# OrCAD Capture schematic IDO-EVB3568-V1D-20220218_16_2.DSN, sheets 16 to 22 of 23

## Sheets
16 P19. Ethernet-GEPHY_RGMII1_M1: size A2; note: Ethernet-GEPHY_RGMII1_M1
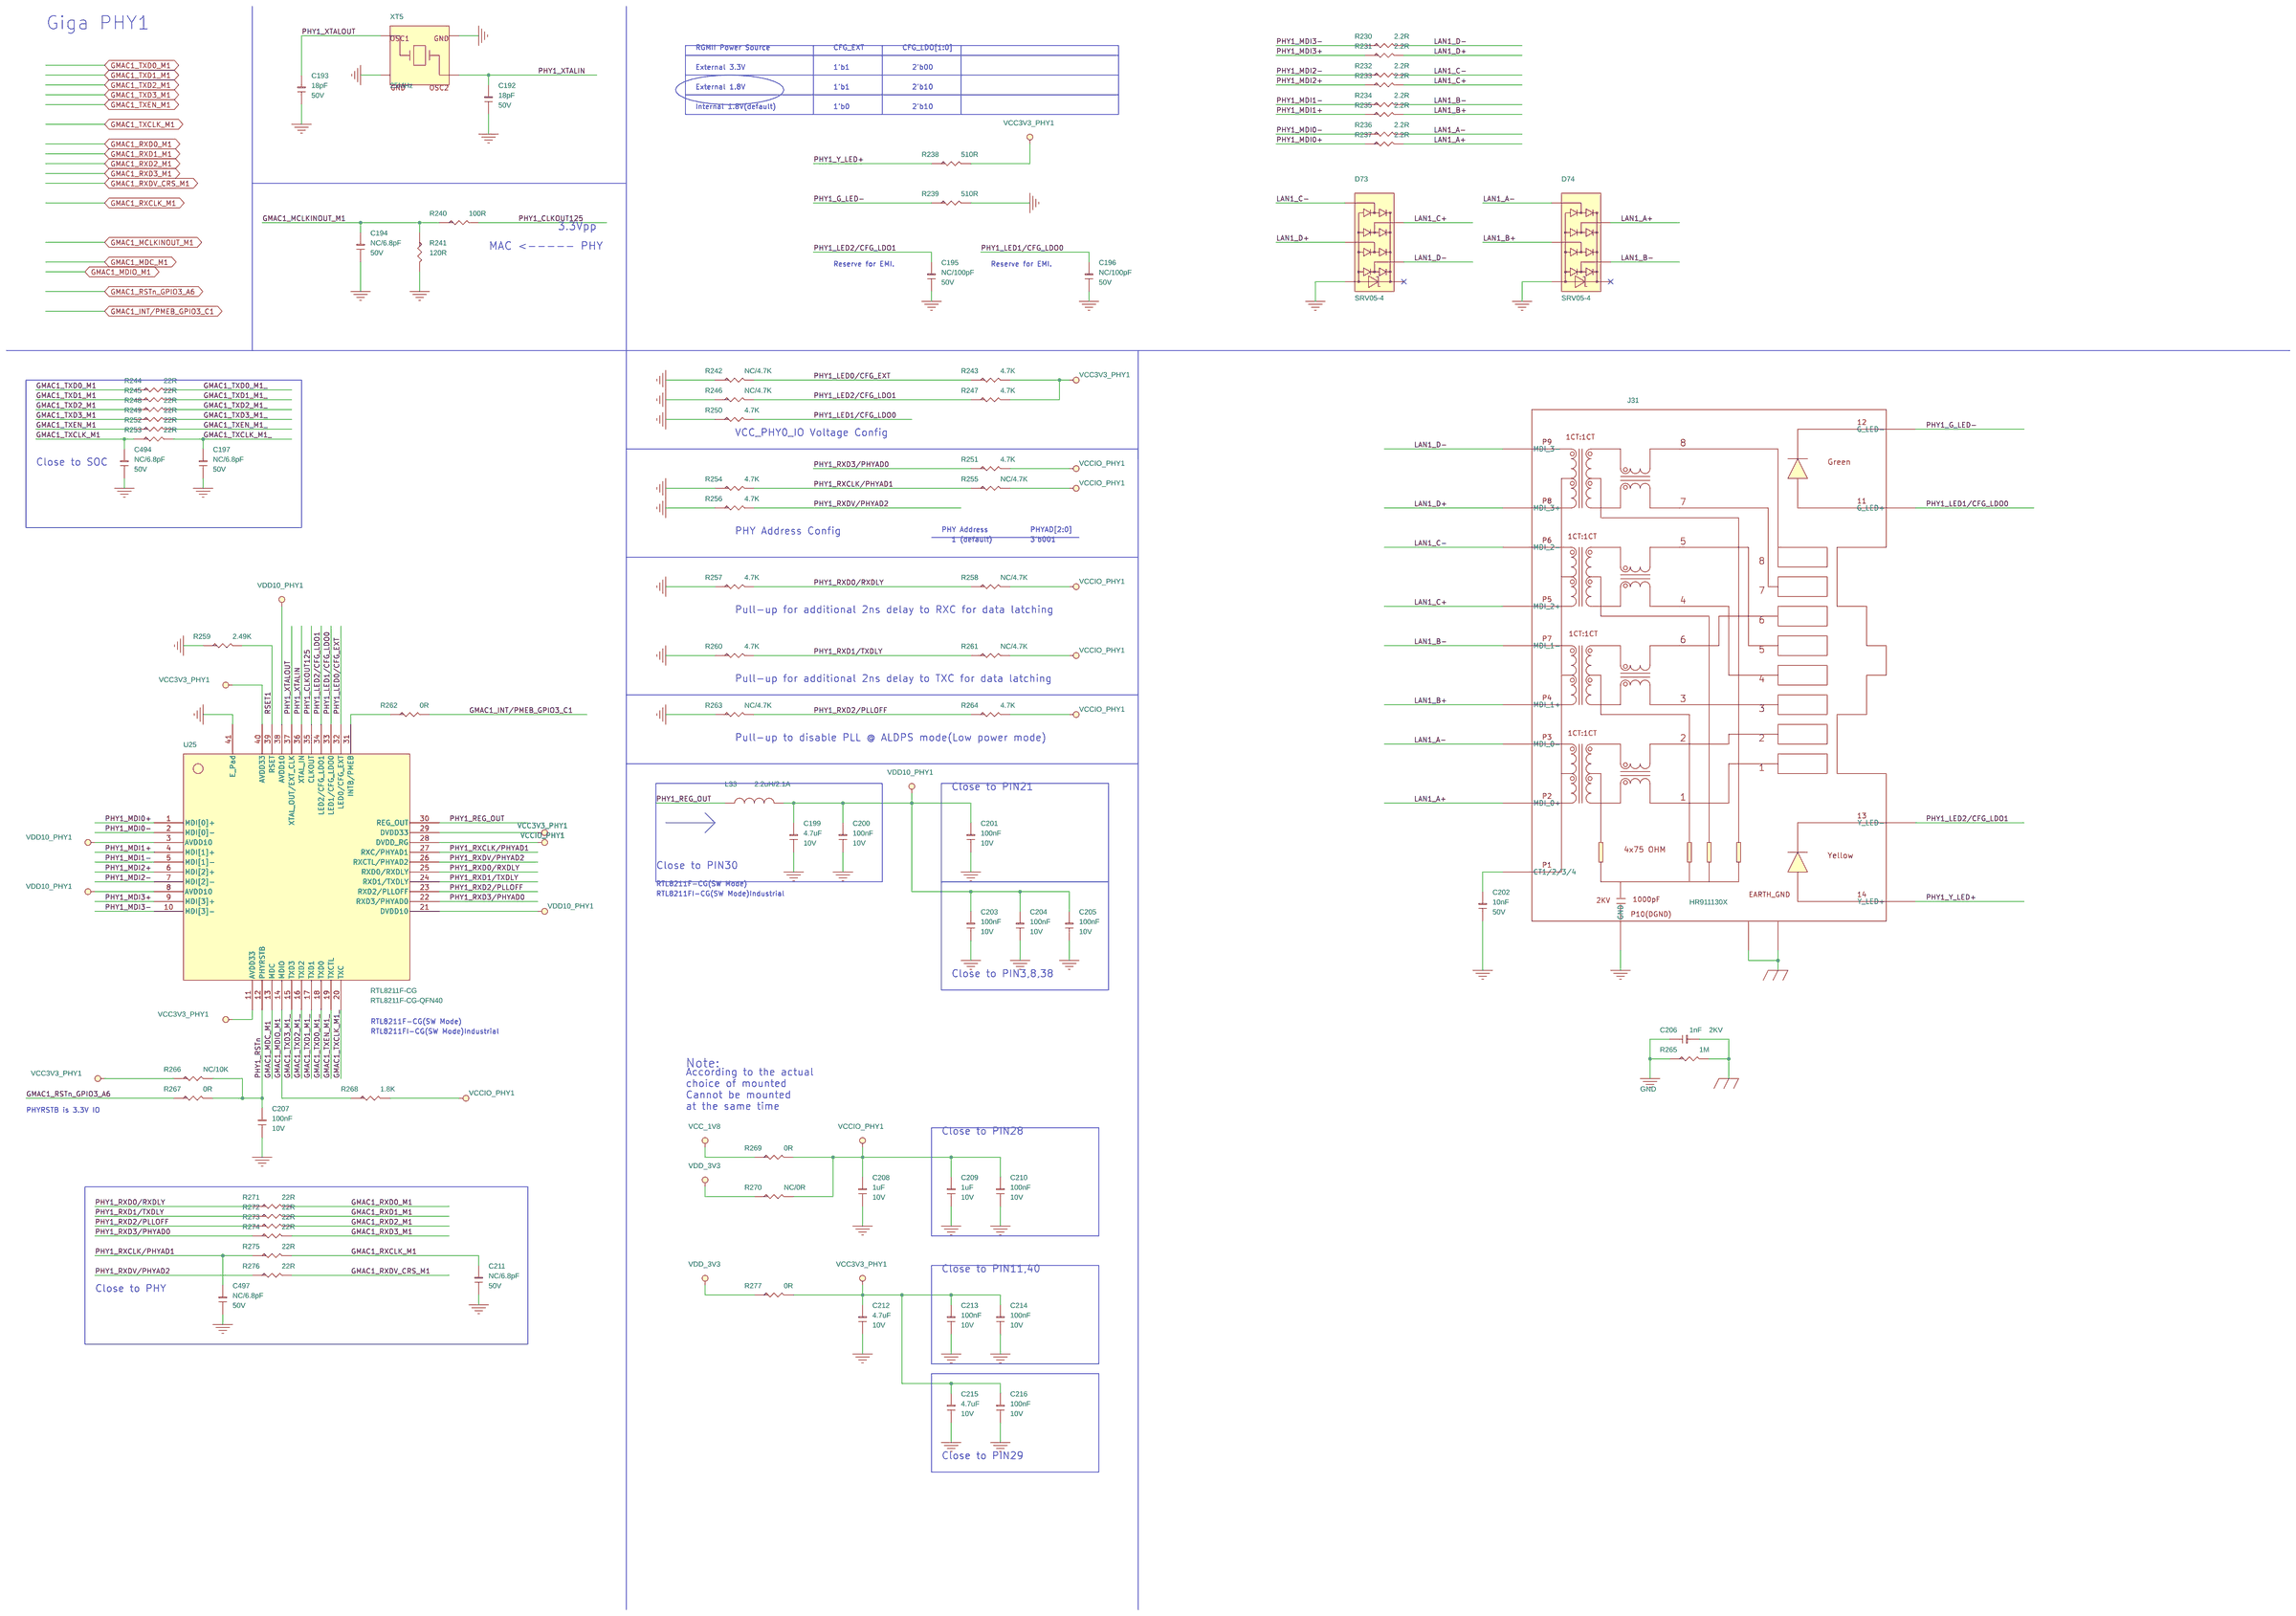
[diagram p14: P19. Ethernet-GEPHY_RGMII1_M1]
17 P23. IO-PCA9593: size A4; note: IO-PCA9593
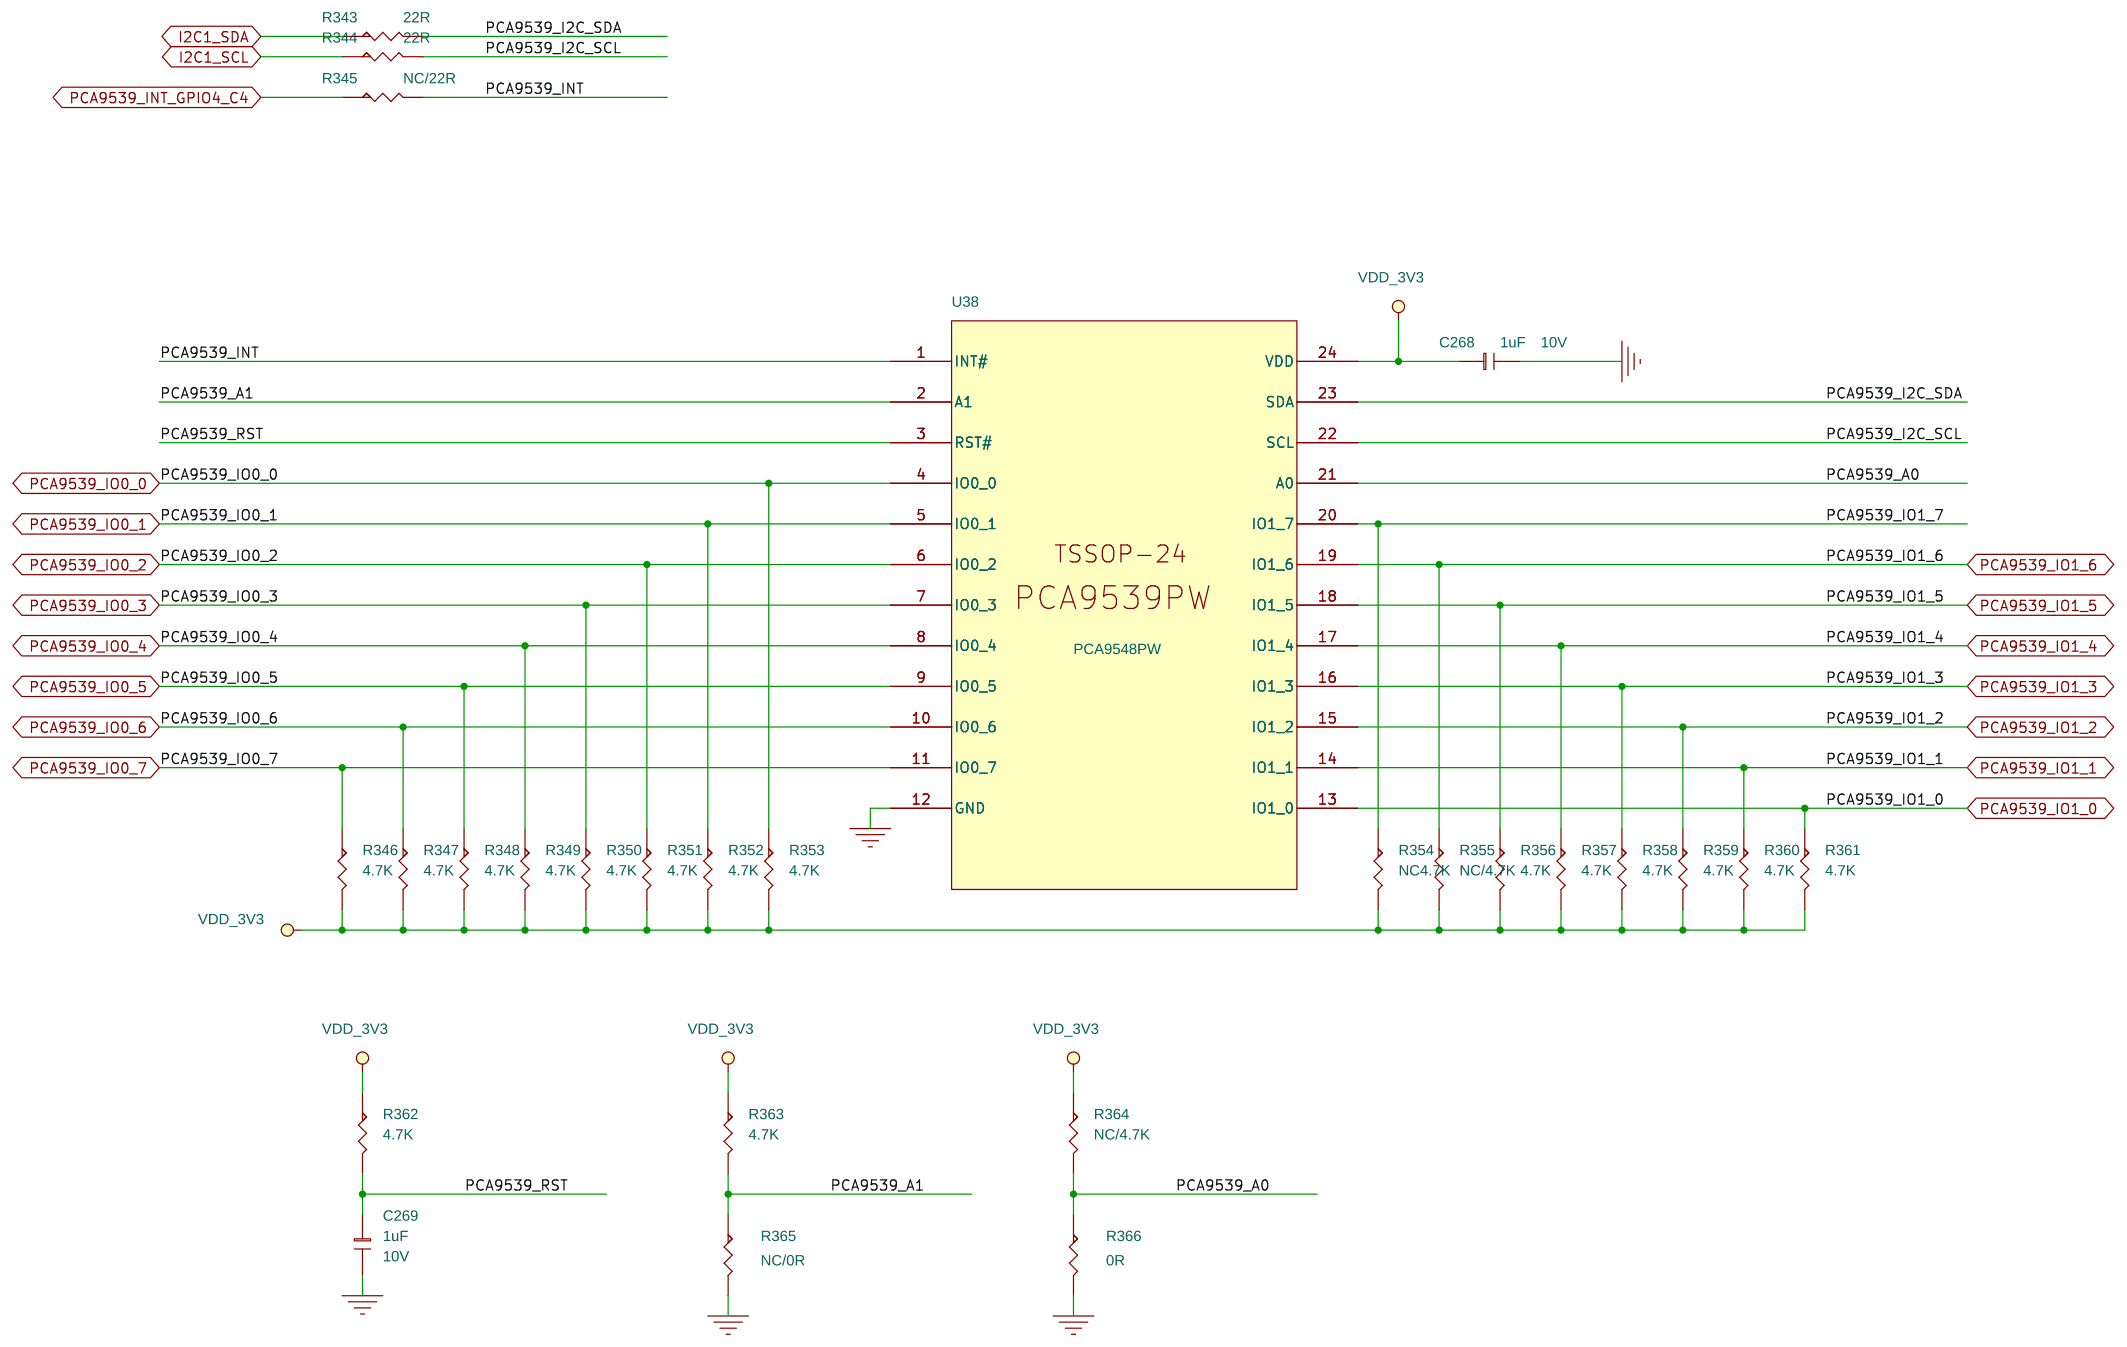
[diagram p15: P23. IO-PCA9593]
18 P21. RTC/SENSOR: size A4; note: RTC/SENSOR
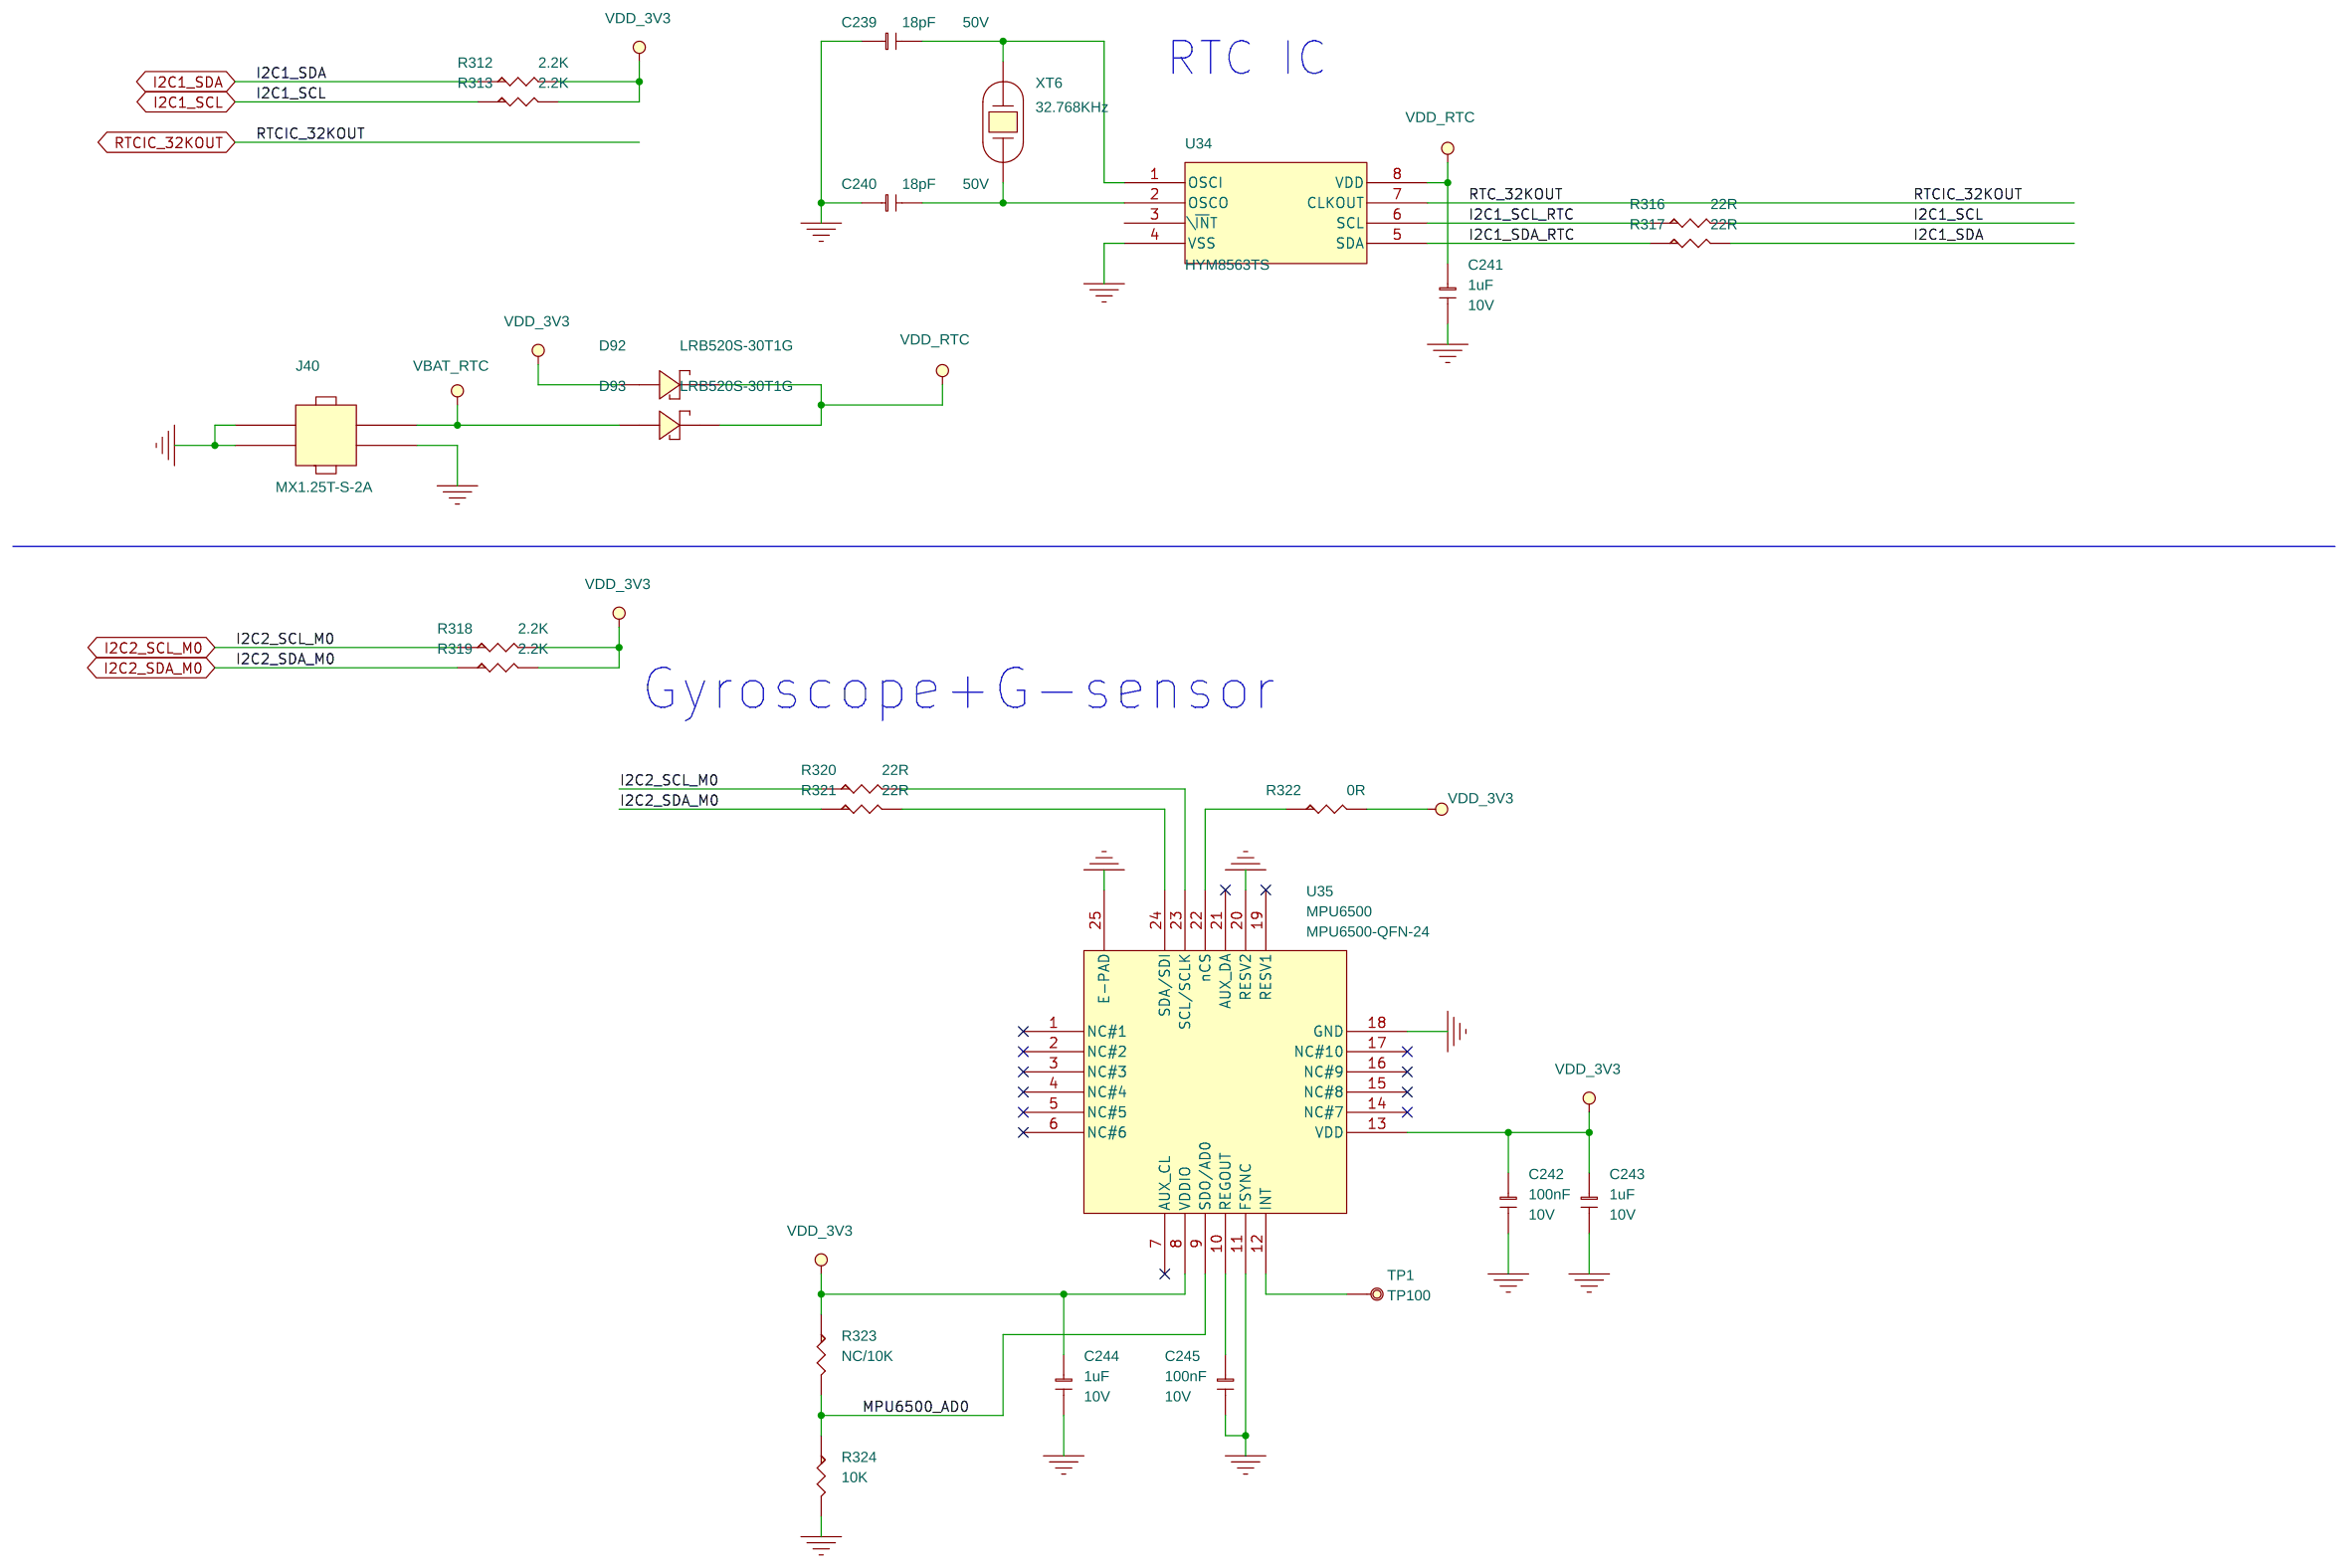
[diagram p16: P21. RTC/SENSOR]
19 P07. USB3.0 Port/SATA: size A3; note: USB3.0 Port
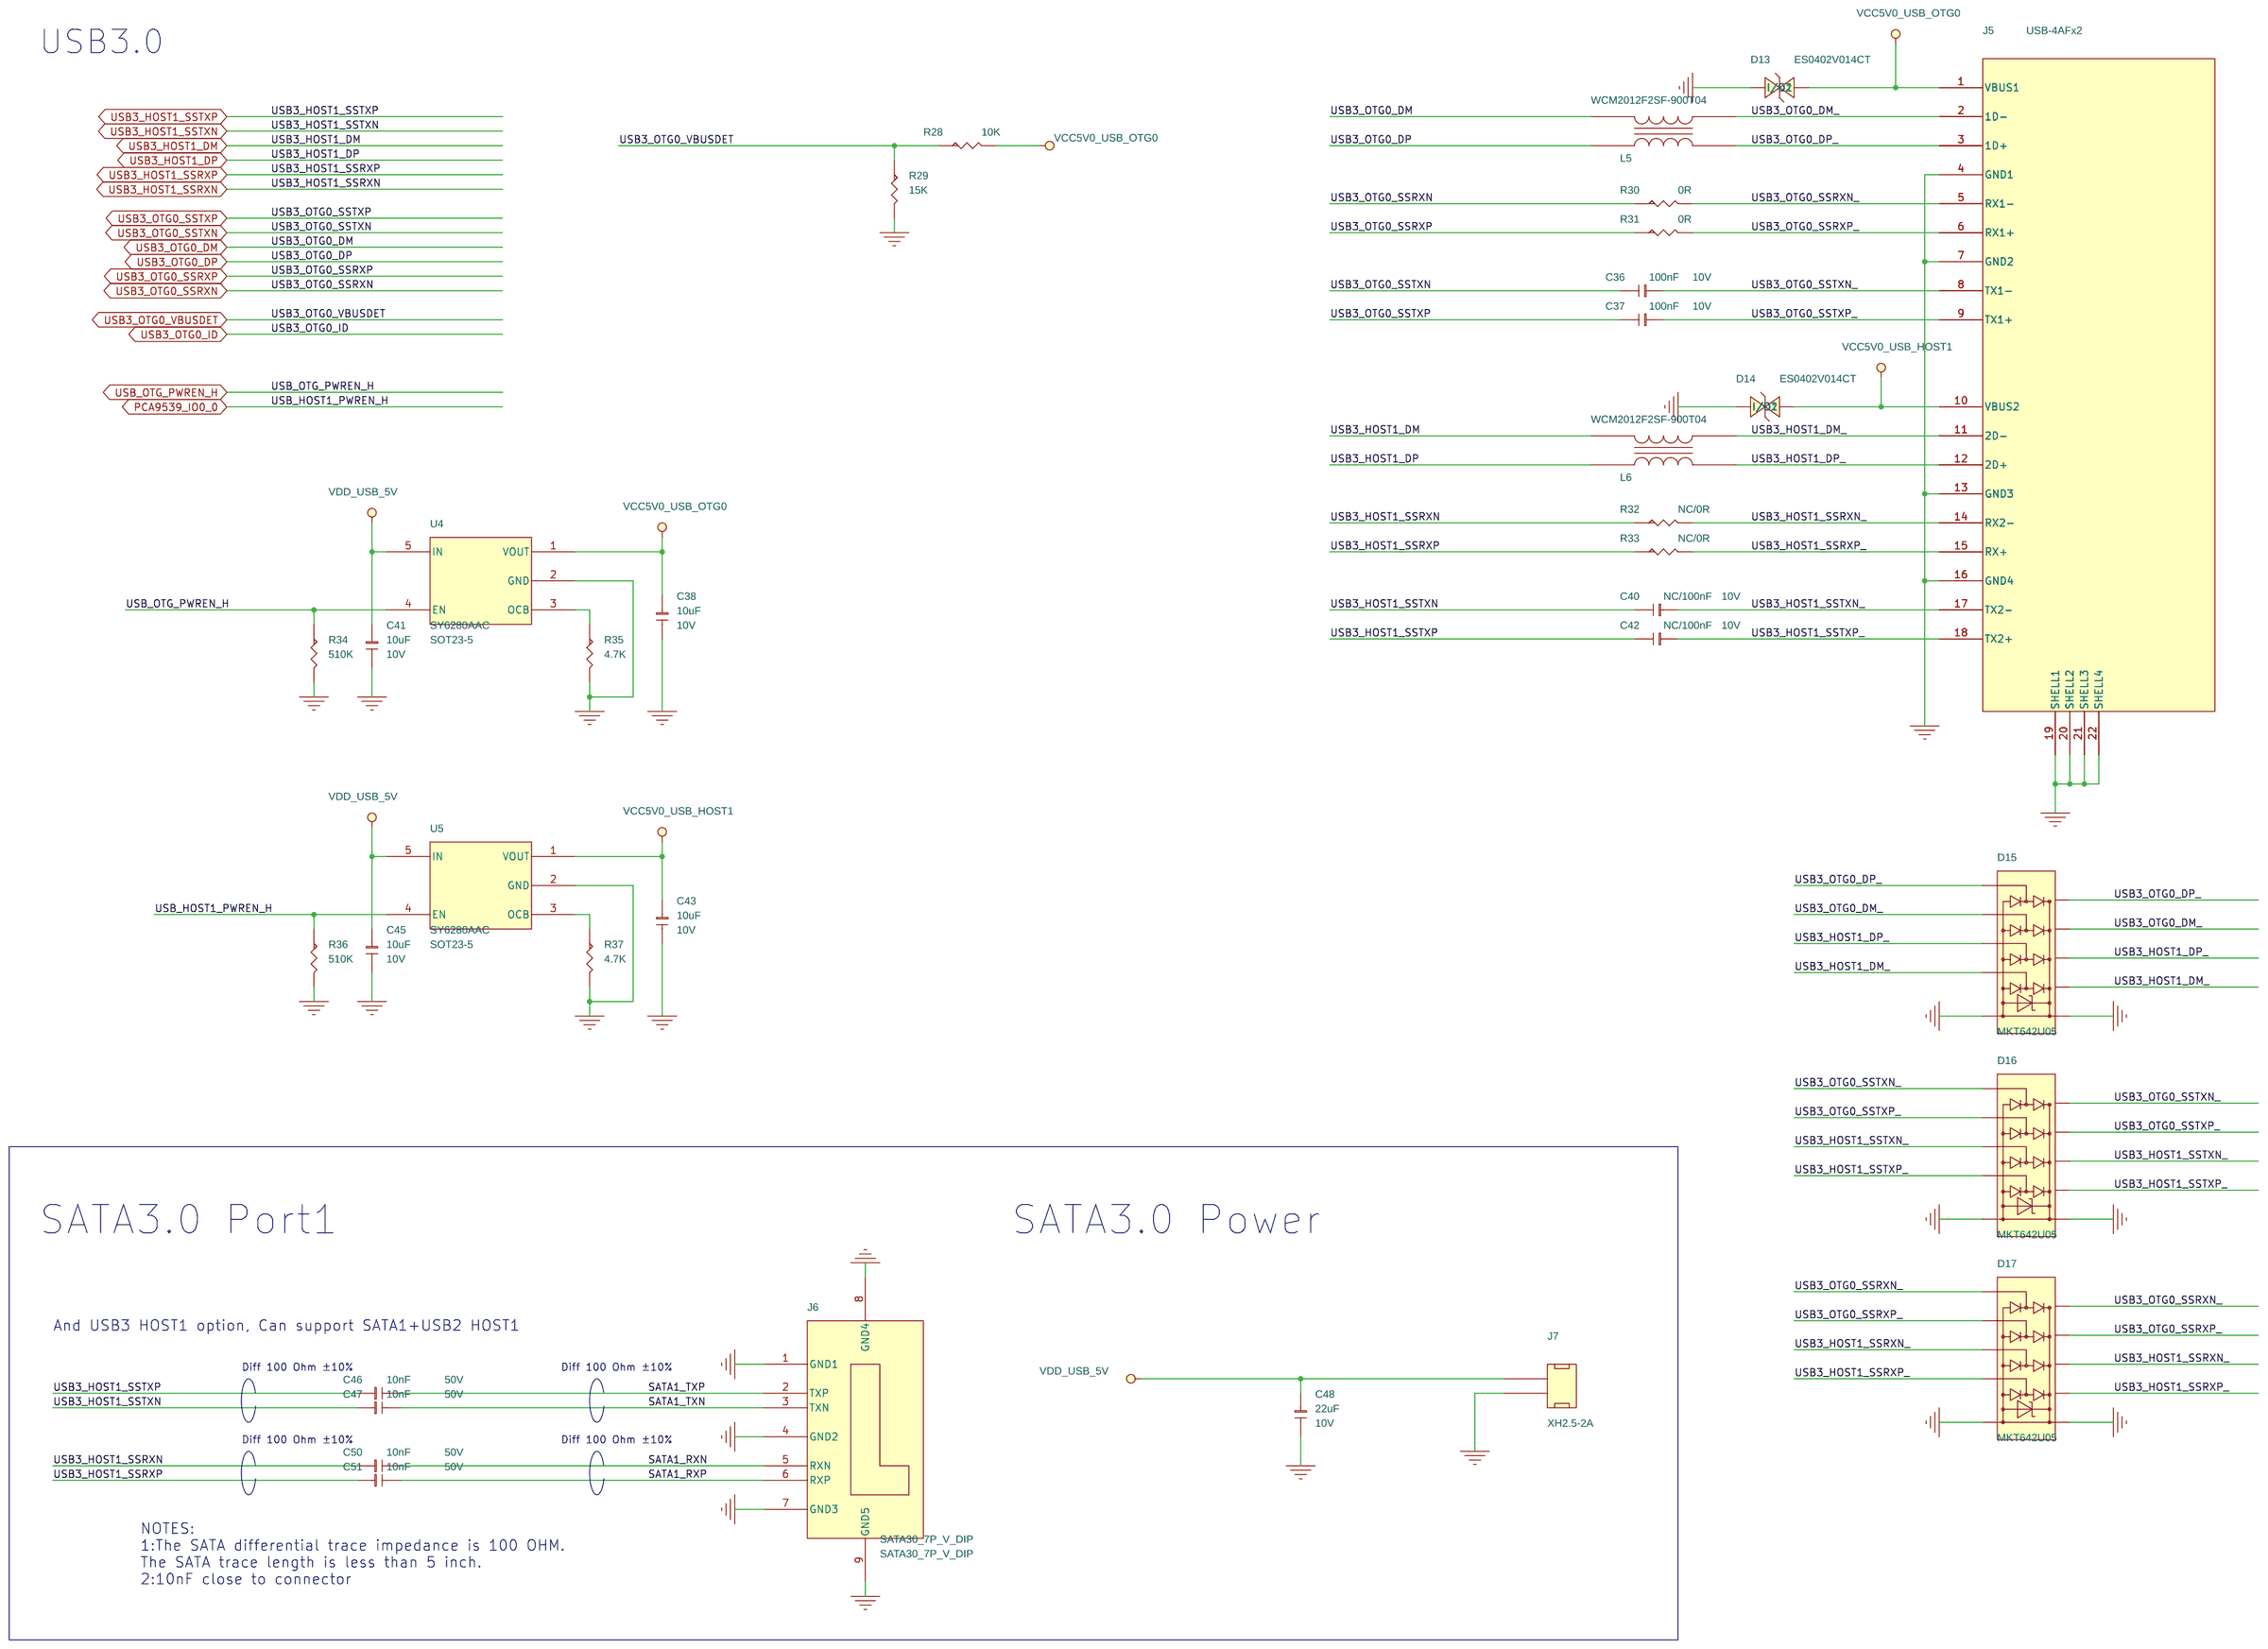
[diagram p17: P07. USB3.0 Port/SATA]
20 P22. M2_NGFF/MINI_PCIE: size A3; note: M2_NGFF/MINI_PCIE
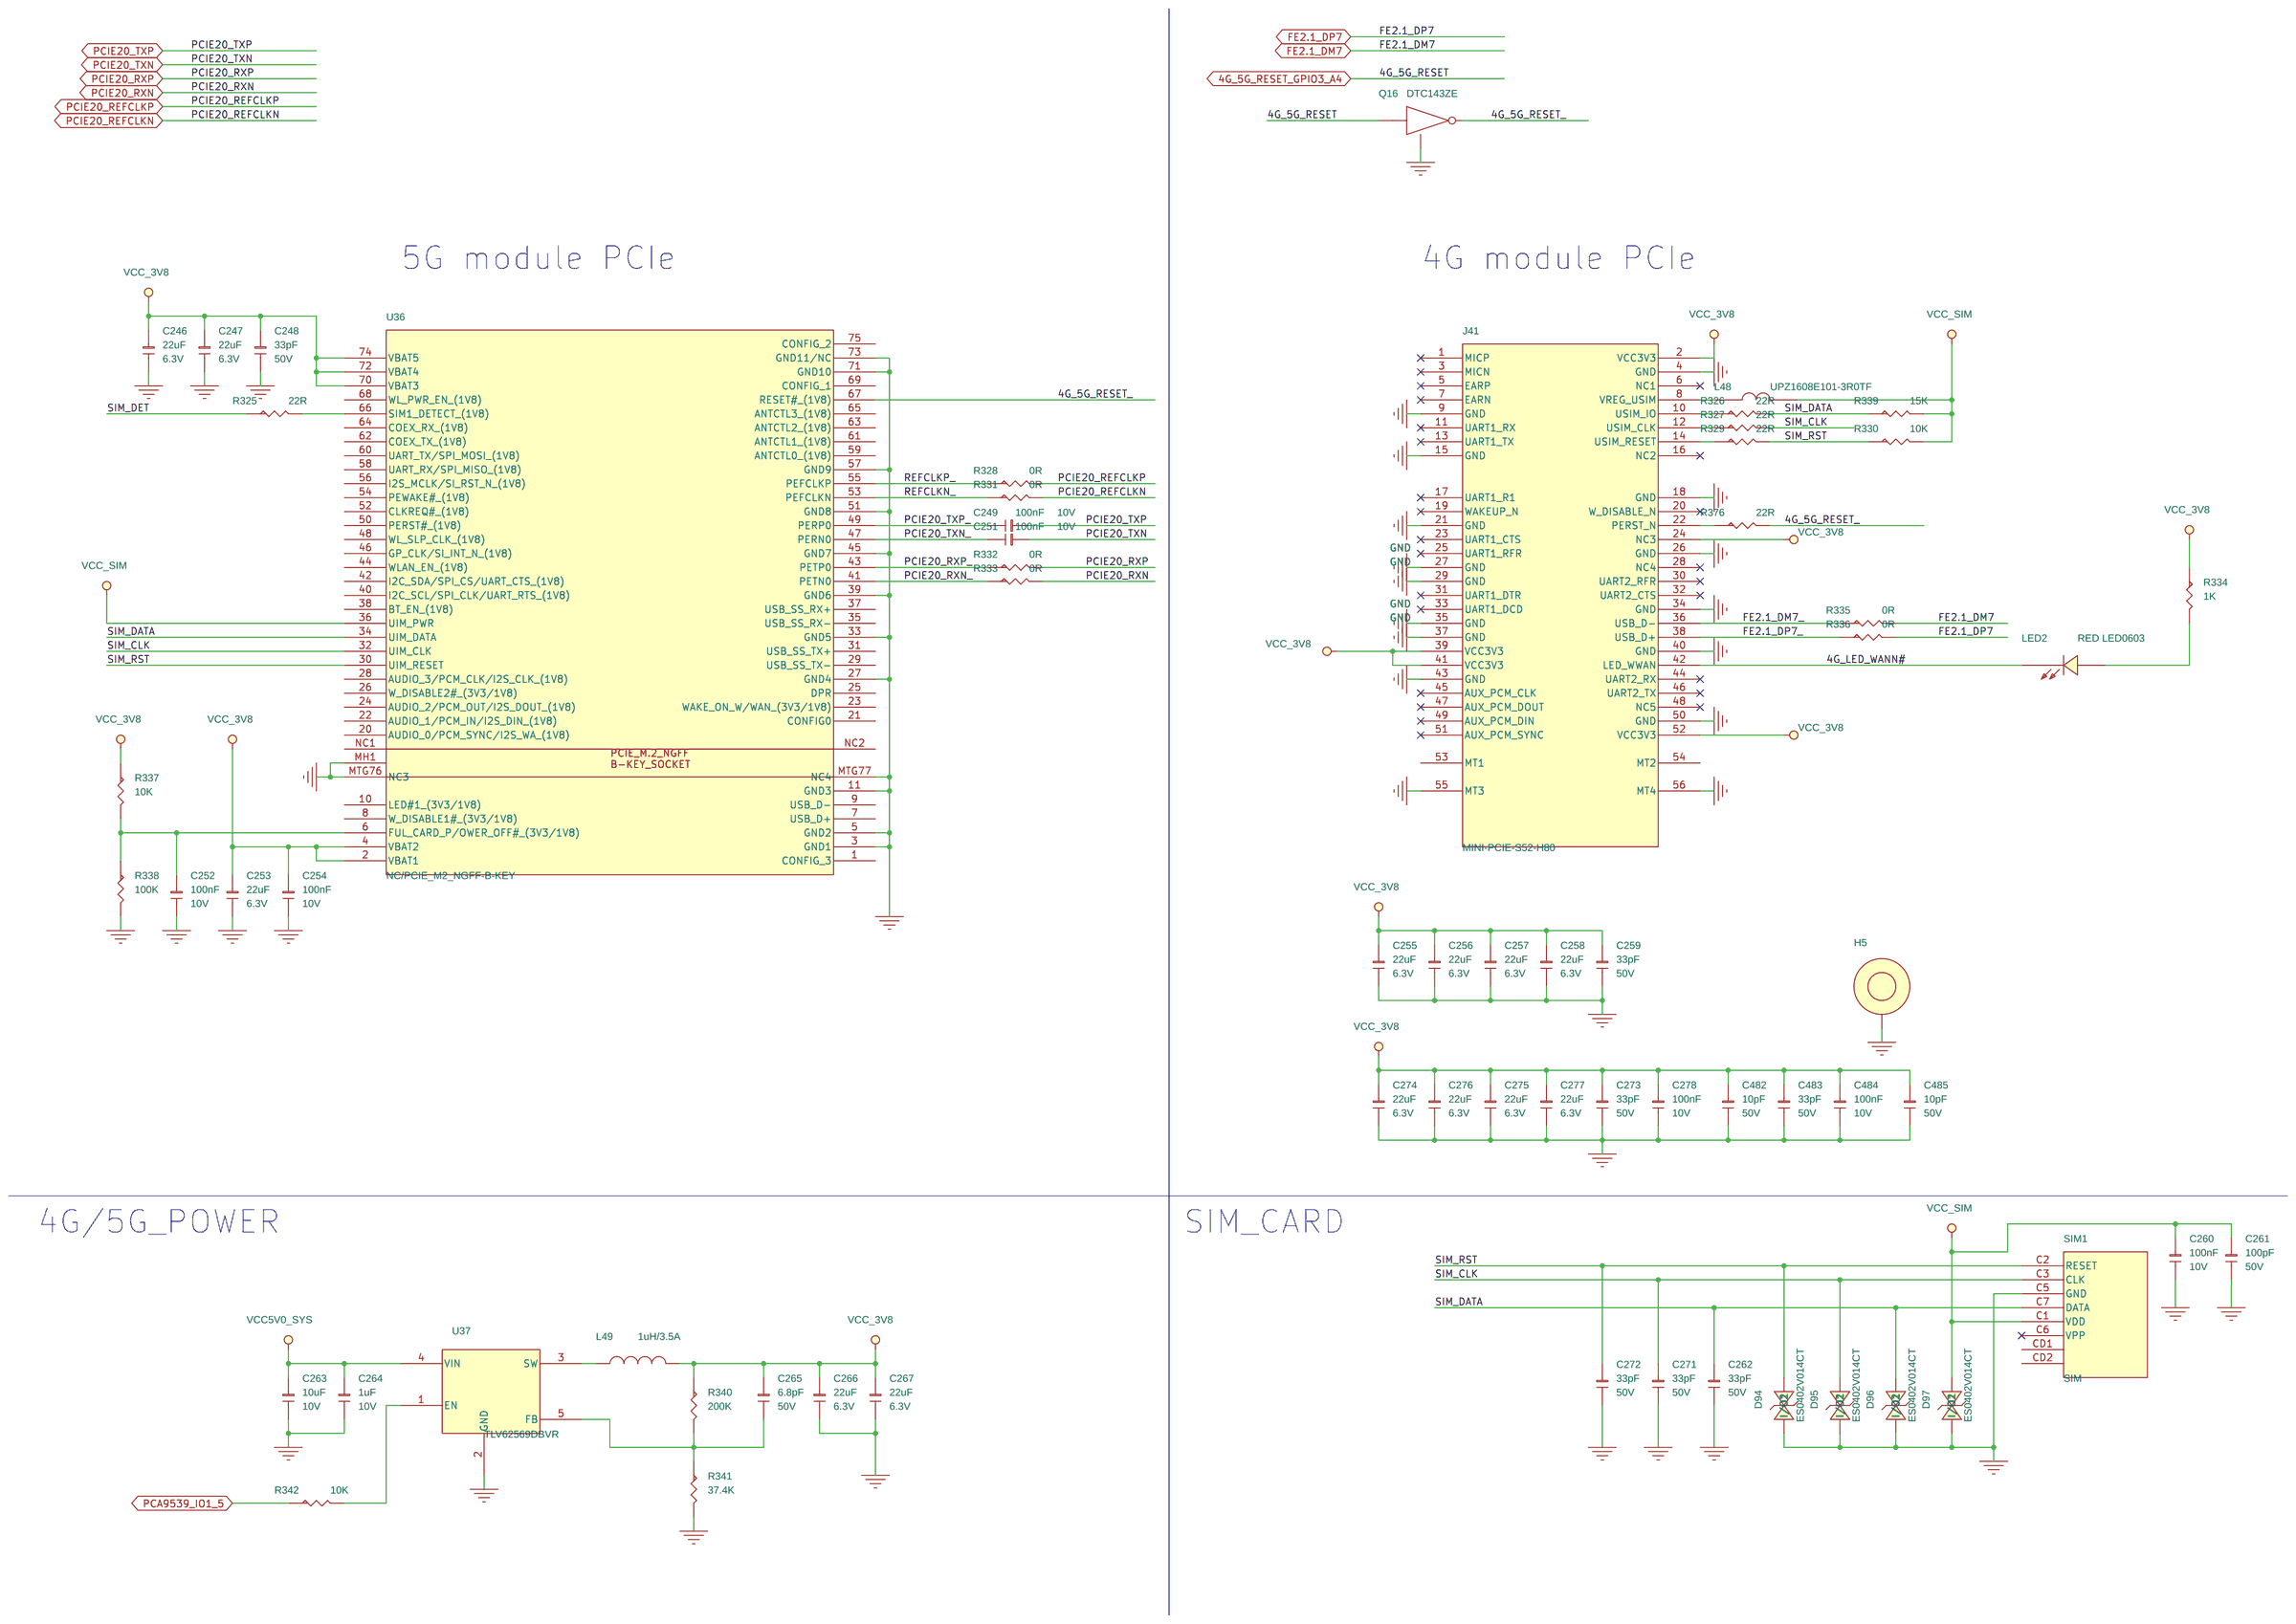
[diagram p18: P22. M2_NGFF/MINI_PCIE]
21 P09. Recovery/IR/SPI/GPIO: size A4; note: Recovery/IR
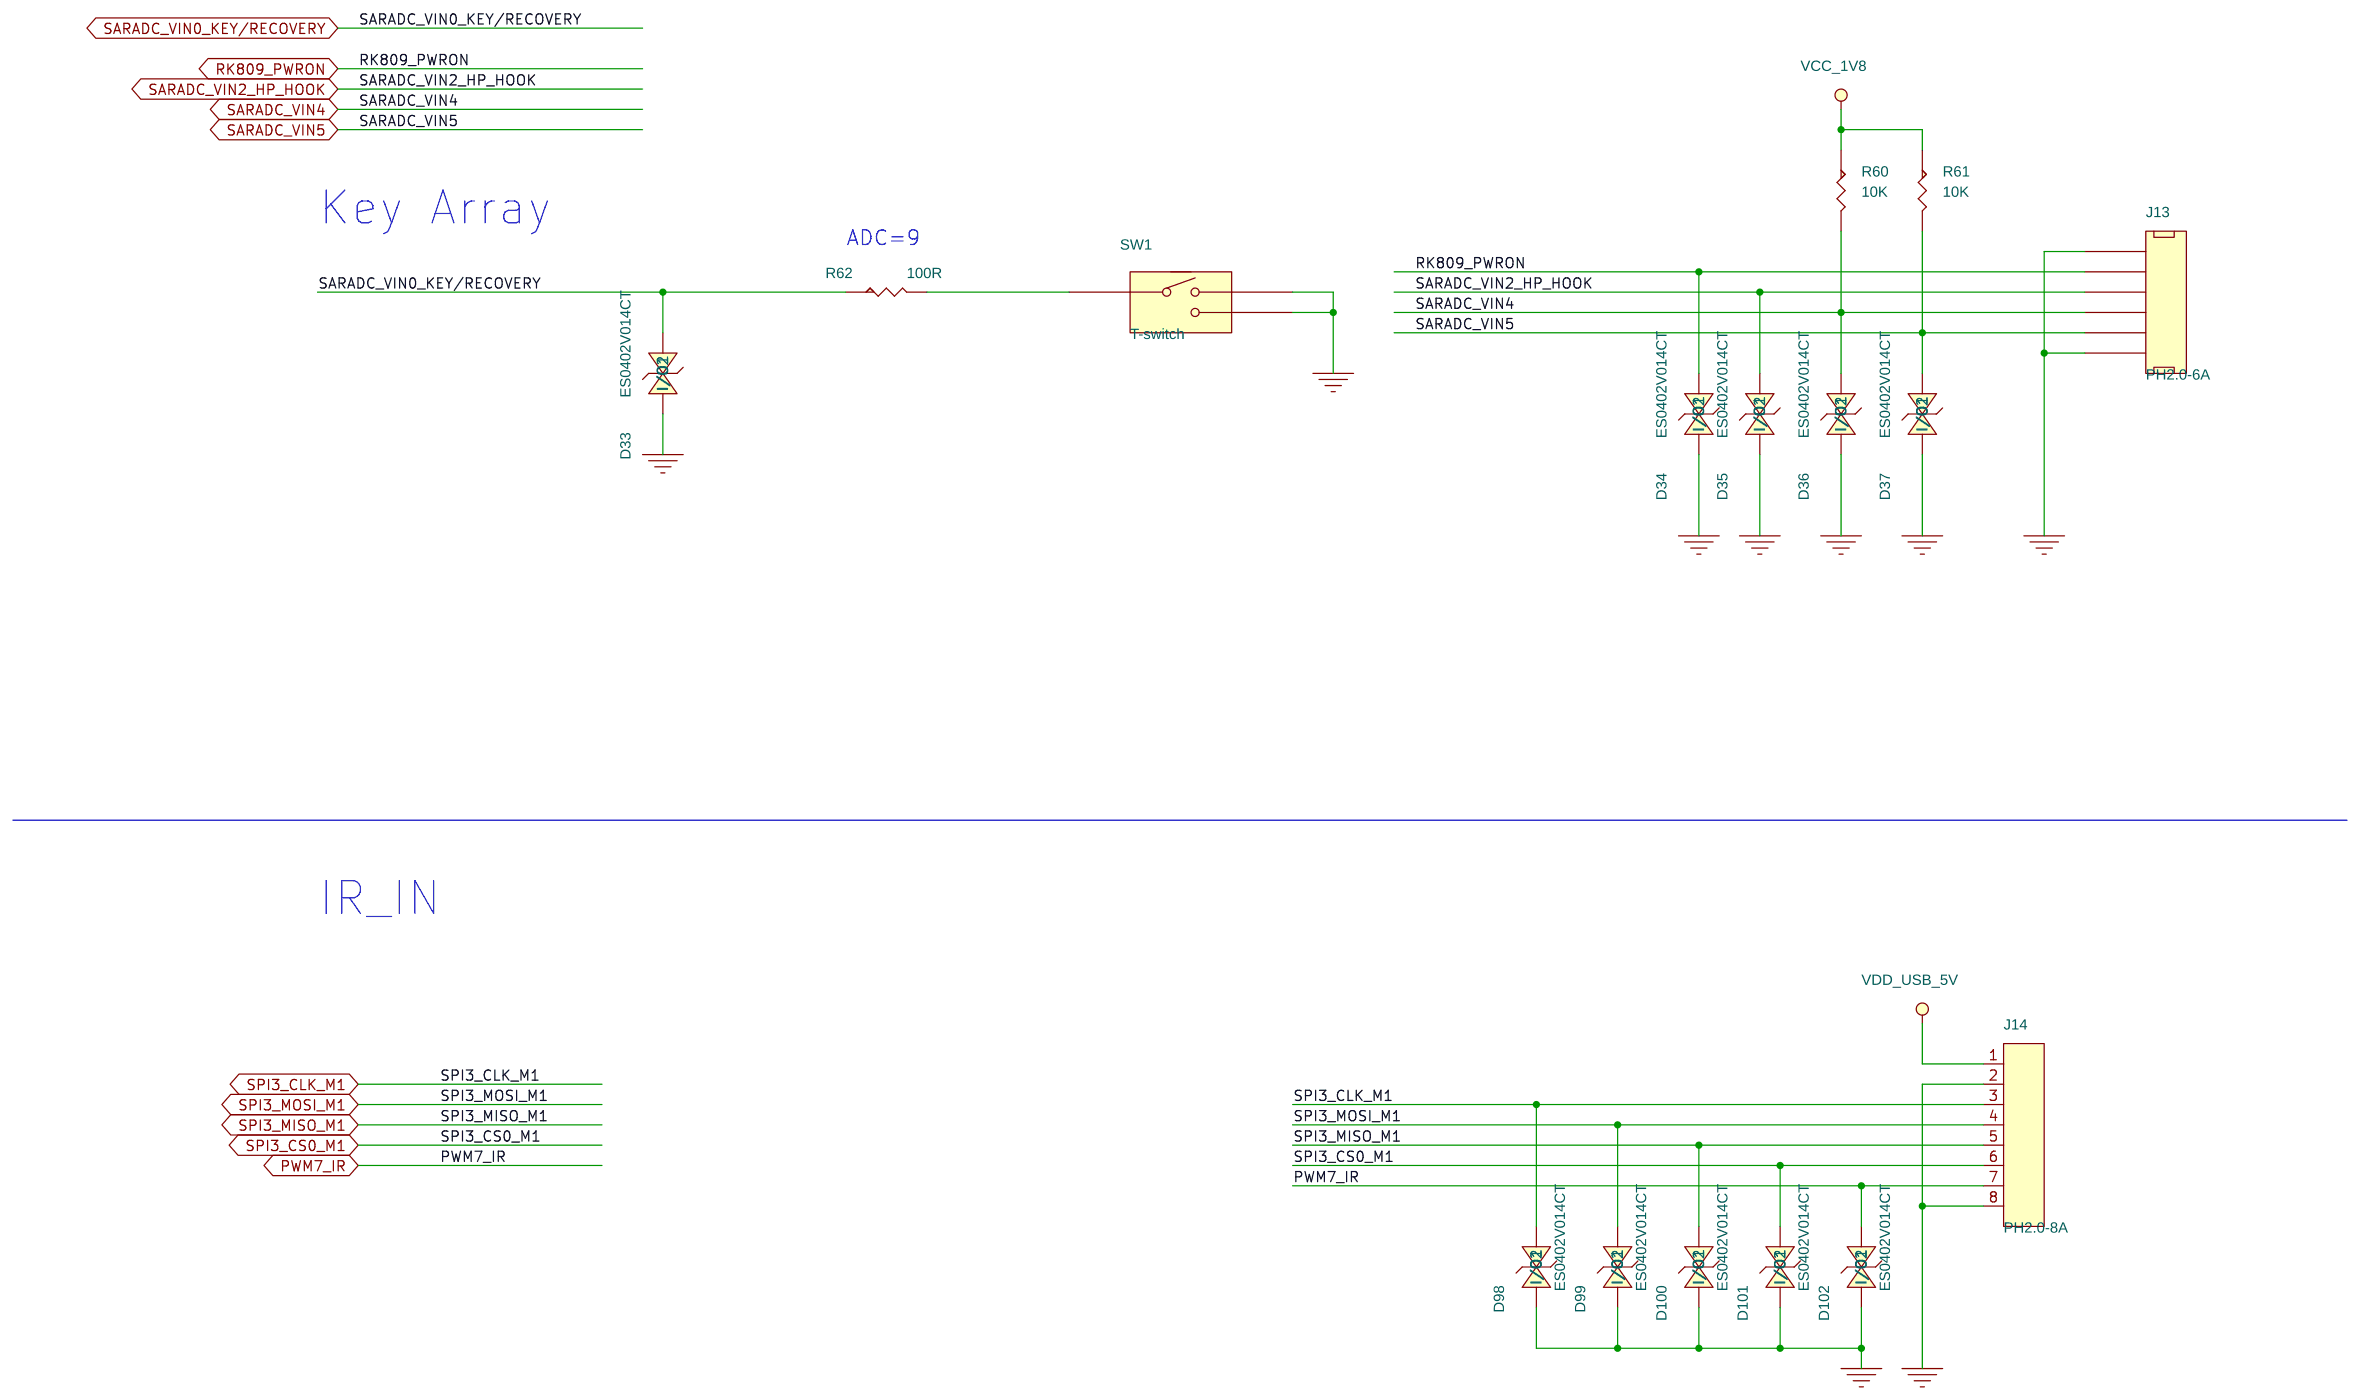
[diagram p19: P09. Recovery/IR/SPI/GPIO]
22 P20. UART/RS232/RS485/CAN: size A2; note: UART/RS232 PORT
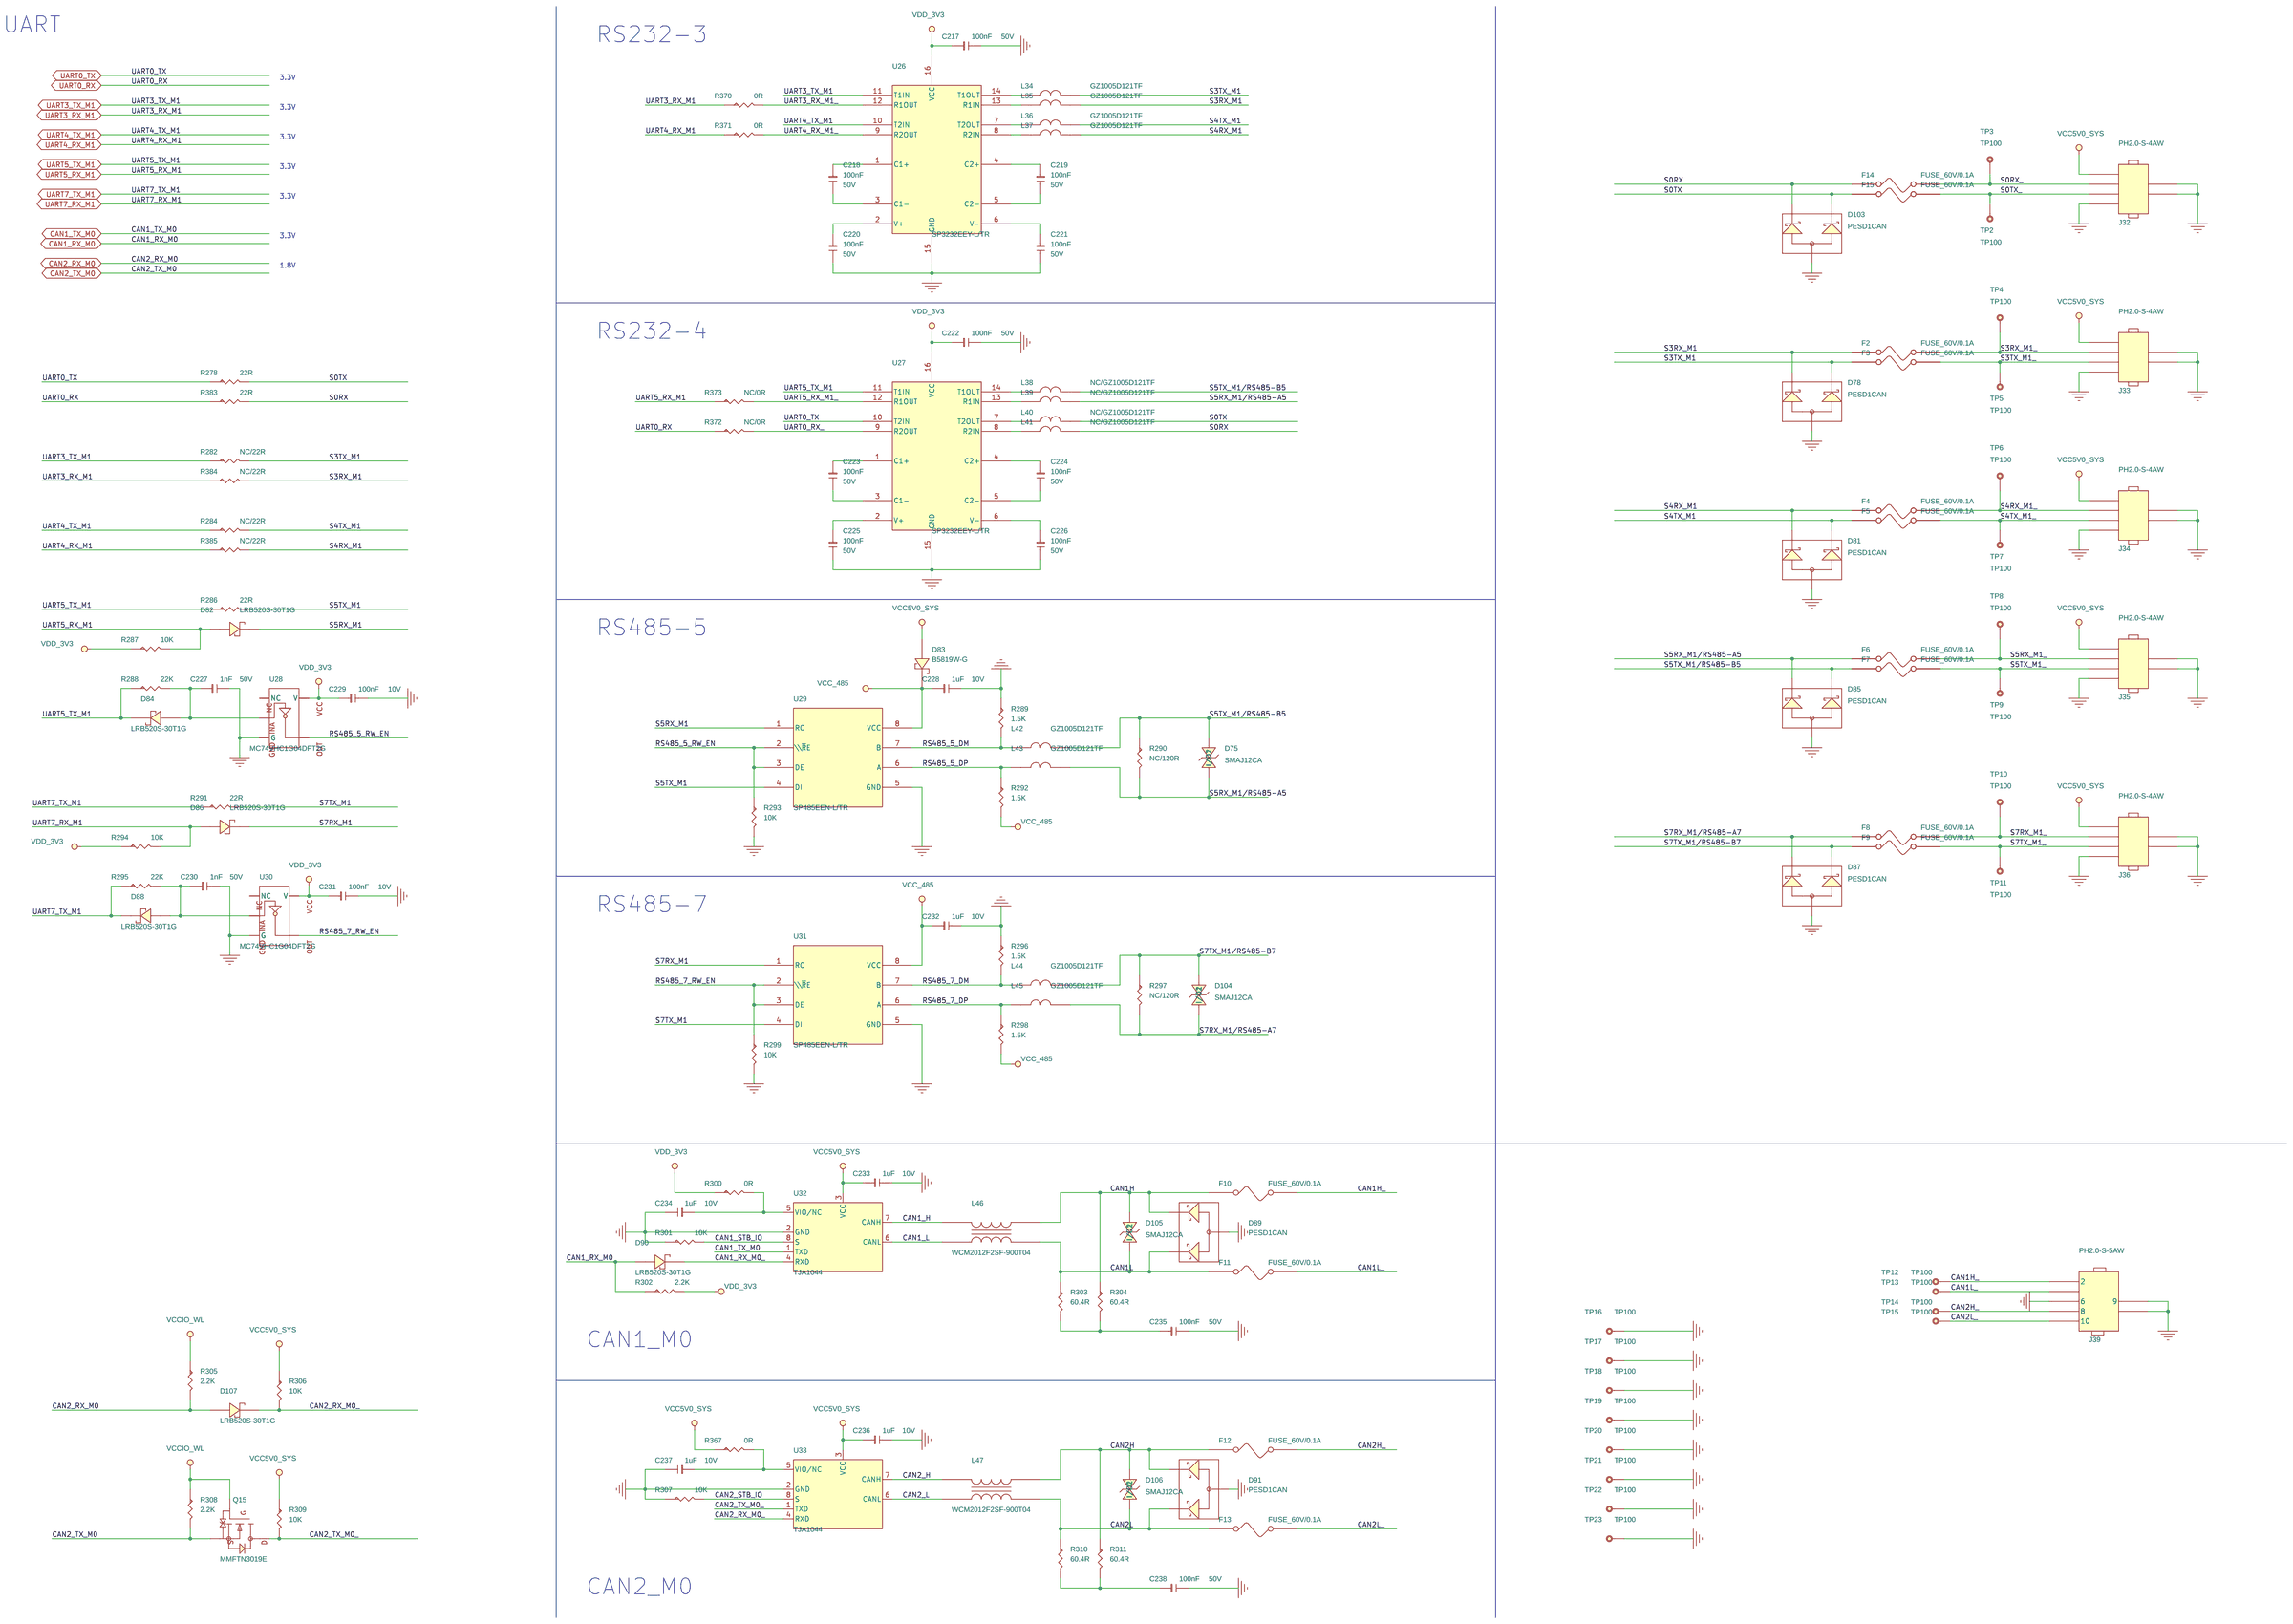
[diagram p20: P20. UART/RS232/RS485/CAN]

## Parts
sheet P07. USB3.0 Port/SATA
C36  100nF  [C0402L]
C37  100nF  [C0402L]
C38  10uF  [C0603L]
C40  NC/100nF  [C0402L]
C41  10uF  [C0603L]
C42  NC/100nF  [C0402L]
C43  10uF  [C0603L]
C45  10uF  [C0603L]
C46  10nF  [C0402L]
C47  10nF  [C0402L]
C48  22uF  [C0805L]
C50  10nF  [C0402L]
C51  10nF  [C0402L]
D13  ES0402V014CT  [V0402]
D14  ES0402V014CT  [V0402]
D15  MKT642U05  [ESD-DFN2510A-10]
D16  MKT642U05  [ESD-DFN2510A-10]
D17  MKT642U05  [ESD-DFN2510A-10]
J5  USB-4AFx2  [USB3D0_AF_18P]
J6  SATA30_7P_V_DIP  [SATA30_7P_V_DIP]
J7  XH2.5-2A  [XH250-2A]
L5  WCM2012F2SF-900T04  [CMLS-ACM2012]
L6  WCM2012F2SF-900T04  [CMLS-ACM2012]
R28  10K  [R0402L]
R29  15K  [R0402L]
R30  0R  [R0402L]
R31  0R  [R0402L]
R32  NC/0R  [R0402L]
R33  NC/0R  [R0402L]
R34  510K  [R0402L]
R35  4.7K  [R0402L]
R36  510K  [R0402L]
R37  4.7K  [R0402L]
U4  SY6280AAC  [SOT23-5]
U5  SY6280AAC  [SOT23-5]
sheet P09. Recovery/IR/SPI/GPIO
D33  ES0402V014CT  [V0402]
D34  ES0402V014CT  [V0402]
D35  ES0402V014CT  [V0402]
D36  ES0402V014CT  [V0402]
D37  ES0402V014CT  [V0402]
D98  ES0402V014CT  [V0402]
D99  ES0402V014CT  [V0402]
D100  ES0402V014CT  [V0402]
D101  ES0402V014CT  [V0402]
D102  ES0402V014CT  [V0402]
J13  PH2.0-6A  [PH200-6A]
J14  PH2.0-8A  [PH200-8A]
R60  10K  [R0402L]
R61  10K  [R0402L]
R62  100R  [R0402L]
SW1  T-switch  [PB-SIDE-P-4_5x4_5]
sheet P19. Ethernet-GEPHY_RGMII1_M1
C192  18pF  [C0402L]
C193  18pF  [C0402L]
C194  NC/6.8pF  [C0402L]
C195  NC/100pF  [C0402L]
C196  NC/100pF  [C0402L]
C197  NC/6.8pF  [C0402L]
C199  4.7uF  [C0402L]
C200  100nF  [C0402L]
C201  100nF  [C0402L]
C202  10nF  [C0402L]
C203  100nF  [C0402L]
C204  100nF  [C0402L]
C205  100nF  [C0402L]
C206  1nF  [C1206L]
C207  100nF  [C0402L]
C208  1uF  [C0402L]
C209  1uF  [C0402L]
C210  100nF  [C0402L]
C211  NC/6.8pF  [C0402L]
C212  4.7uF  [C0402L]
C213  100nF  [C0402L]
C214  100nF  [C0402L]
C215  4.7uF  [C0402L]
C216  100nF  [C0402L]
C494  NC/6.8pF  [C0402L]
C497  NC/6.8pF  [C0402L]
D73  SRV05-4  [SOT23-6]
D74  SRV05-4  [SOT23-6]
J31  HR911130X  [HR911130X]
L33  2.2uH/2.1A  [L2520]
R230  2.2R  [R0402L]
R231  2.2R  [R0402L]
R232  2.2R  [R0402L]
R233  2.2R  [R0402L]
R234  2.2R  [R0402L]
R235  2.2R  [R0402L]
R236  2.2R  [R0402L]
R237  2.2R  [R0402L]
R238  510R  [R0402L]
R239  510R  [R0402L]
R240  100R  [R0402L]
R241  120R  [R0402L]
R242  NC/4.7K  [R0402L]
R243  4.7K  [R0402L]
R244  22R  [R0402L]
R245  22R  [R0402L]
R246  NC/4.7K  [R0402L]
R247  4.7K  [R0402L]
R248  22R  [R0402L]
R249  22R  [R0402L]
R250  4.7K  [R0402L]
R251  4.7K  [R0402L]
R252  22R  [R0402L]
R253  22R  [R0402L]
R254  4.7K  [R0402L]
R255  NC/4.7K  [R0402L]
R256  4.7K  [R0402L]
R257  4.7K  [R0402L]
R258  NC/4.7K  [R0402L]
R259  2.49K  [R0402L]
R260  4.7K  [R0402L]
R261  NC/4.7K  [R0402L]
R262  0R  [R0402L]
R263  NC/4.7K  [R0402L]
R264  4.7K  [R0402L]
R265  1M  [R0805L]
R266  NC/10K  [R0402L]
R267  0R  [R0402L]
R268  1.8K  [R0402L]
R269  0R  [R0402L]
R270  NC/0R  [R0402L]
R271  22R  [R0402L]
R272  22R  [R0402L]
R273  22R  [R0402L]
R274  22R  [R0402L]
R275  22R  [R0402L]
R276  22R  [R0402L]
R277  0R  [R0402L]
U25  RTL8211F-CG  [RTL8211F-CG-QFN40]
XT5  25MHz  [xtal_32x25_4p]
sheet P20. UART/RS232/RS485/CAN
C217  100nF  [C0402L]
C218  100nF  [C0402L]
C219  100nF  [C0402L]
C220  100nF  [C0402L]
C221  100nF  [C0402L]
C222  100nF  [C0402L]
C223  100nF  [C0402L]
C224  100nF  [C0402L]
C225  100nF  [C0402L]
C226  100nF  [C0402L]
C227  1nF  [C0402L]
C228  1uF  [C0402L]
C229  100nF  [C0402L]
C230  1nF  [C0402L]
C231  100nF  [C0402L]
C232  1uF  [C0402L]
C233  1uF  [C0402L]
C234  1uF  [C0402L]
C235  100nF  [C0402L]
C236  1uF  [C0402L]
C237  1uF  [C0402L]
C238  100nF  [C0402L]
D75  SMAJ12CA  [SMA_DO-214AC]
D78  PESD1CAN  [SOT23]
D81  PESD1CAN  [SOT23]
D82  LRB520S-30T1G  [SOD523]
D83  B5819W-G  [SOD123]
D84  LRB520S-30T1G  [SOD523]
D85  PESD1CAN  [SOT23]
D86  LRB520S-30T1G  [SOD523]
D87  PESD1CAN  [SOT23]
D88  LRB520S-30T1G  [SOD523]
D89  PESD1CAN  [SOT23]
D90  LRB520S-30T1G  [SOD523]
D91  PESD1CAN  [SOT23]
D103  PESD1CAN  [SOT23]
D104  SMAJ12CA  [SMA_DO-214AC]
D105  SMAJ12CA  [SMA_DO-214AC]
D106  SMAJ12CA  [SMA_DO-214AC]
D107  LRB520S-30T1G  [SOD523]
F2  FUSE_60V/0.1A  [SMD1206]
F3  FUSE_60V/0.1A  [SMD1206]
F4  FUSE_60V/0.1A  [SMD1206]
F5  FUSE_60V/0.1A  [SMD1206]
F6  FUSE_60V/0.1A  [SMD1206]
F7  FUSE_60V/0.1A  [SMD1206]
F8  FUSE_60V/0.1A  [SMD1206]
F9  FUSE_60V/0.1A  [SMD1206]
F10  FUSE_60V/0.1A  [SMD1206]
F11  FUSE_60V/0.1A  [SMD1206]
F12  FUSE_60V/0.1A  [SMD1206]
F13  FUSE_60V/0.1A  [SMD1206]
F14  FUSE_60V/0.1A  [SMD1206]
F15  FUSE_60V/0.1A  [SMD1206]
J32  PH2.0-S-4AW  [PH200-S-4AWZ]
J33  PH2.0-S-4AW  [PH200-S-4AWZ]
J34  PH2.0-S-4AW  [PH200-S-4AWZ]
J35  PH2.0-S-4AW  [PH200-S-4AWZ]
J36  PH2.0-S-4AW  [PH200-S-4AWZ]
J39  PH2.0-S-5AW  [PH200-S-5AWZ]
L34  GZ1005D121TF  [L0402]
L35  GZ1005D121TF  [L0402]
L36  GZ1005D121TF  [L0402]
L37  GZ1005D121TF  [L0402]
L38  NC/GZ1005D121TF  [L0402]
L39  NC/GZ1005D121TF  [L0402]
L40  NC/GZ1005D121TF  [L0402]
L41  NC/GZ1005D121TF  [L0402]
L42  GZ1005D121TF  [L0402]
L43  GZ1005D121TF  [L0402]
L44  GZ1005D121TF  [L0402]
L45  GZ1005D121TF  [L0402]
L46  WCM2012F2SF-900T04  [CMLS-ACM2012]
L47  WCM2012F2SF-900T04  [CMLS-ACM2012]
Q15  MMFTN3019E  [SOT523]
R278  22R  [R0402L]
R282  NC/22R  [R0402L]
R284  NC/22R  [R0402L]
R286  22R  [R0402L]
R287  10K  [R0402L]
R288  22K  [R0402L]
R289  1.5K  [R0603L]
R290  NC/120R  [R1206L]
R291  22R  [R0402L]
R292  1.5K  [R0603L]
R293  10K  [R0402L]
R294  10K  [R0402L]
R295  22K  [R0402L]
R296  1.5K  [R0603L]
R297  NC/120R  [R1206L]
R298  1.5K  [R0603L]
R299  10K  [R0402L]
R300  0R  [R0402L]
R301  10K  [R0402L]
R302  2.2K  [R0402L]
R303  60.4R  [R0603L]
R304  60.4R  [R0603L]
R305  2.2K  [R0402L]
R306  10K  [R0402L]
R307  10K  [R0402L]
R308  2.2K  [R0402L]
R309  10K  [R0402L]
R310  60.4R  [R0603L]
R311  60.4R  [R0603L]
R367  0R  [R0402L]
R370  0R  [R0402L]
R371  0R  [R0402L]
R372  NC/0R  [R0402L]
R373  NC/0R  [R0402L]
R383  22R  [R0402L]
R384  NC/22R  [R0402L]
R385  NC/22R  [R0402L]
TP2  TP100  [TP100]
TP3  TP100  [TP100]
TP4  TP100  [TP100]
TP5  TP100  [TP100]
TP6  TP100  [TP100]
TP7  TP100  [TP100]
TP8  TP100  [TP100]
TP9  TP100  [TP100]
TP10  TP100  [TP100]
TP11  TP100  [TP100]
TP12  TP100  [TP100]
TP13  TP100  [TP100]
TP14  TP100  [TP100]
TP15  TP100  [TP100]
TP16  TP100  [TP100]
TP17  TP100  [TP100]
TP18  TP100  [TP100]
TP19  TP100  [TP100]
TP20  TP100  [TP100]
TP21  TP100  [TP100]
TP22  TP100  [TP100]
TP23  TP100  [TP100]
U26  SP3232EEY-L/TR  [SP3232EEY-TSSOP-16]
U27  SP3232EEY-L/TR  [SP3232EEY-TSSOP-16]
U28  MC74VHC1G04DFT2G  [SOT353]
U29  SP485EEN-L/TR  [SOP8-P127-390X490]
U30  MC74VHC1G04DFT2G  [SOT353]
U31  SP485EEN-L/TR  [SOP8-P127-390X490]
U32  TJA1044  [SOP8-P127-390X490]
U33  TJA1044  [SOP8-P127-390X490]
sheet P21. RTC/SENSOR
C239  18pF  [C0402L]
C240  18pF  [C0402L]
C241  1uF  [C0402L]
C242  100nF  [C0402L]
C243  1uF  [C0402L]
C244  1uF  [C0402L]
C245  100nF  [C0402L]
D92  LRB520S-30T1G  [SOD523]
D93  LRB520S-30T1G  [SOD523]
J40  MX1.25T-S-2A  [MX125T-S-2A]
R312  2.2K  [R0402L]
R313  2.2K  [R0402L]
R316  22R  [R0402L]
R317  22R  [R0402L]
R318  2.2K  [R0402L]
R319  2.2K  [R0402L]
R320  22R  [R0402L]
R321  22R  [R0402L]
R322  0R  [R0402L]
R323  NC/10K  [R0402L]
R324  10K  [R0402L]
TP1  TP100  [TP100]
U34  HYM8563TS  [PCF85063ATT-TSSOP8]
U35  MPU6500  [MPU6500-QFN-24]
XT6  32.768KHz  [XTAL_32X15_2P]
sheet P22. M2_NGFF/MINI_PCIE
C246  22uF  [C0603L]
C247  22uF  [C0603L]
C248  33pF  [C0402L]
C249  100nF  [C0402L]
C251  100nF  [C0402L]
C252  100nF  [C0402L]
C253  22uF  [C0603L]
C254  100nF  [C0402L]
C255  22uF  [C0603L]
C256  22uF  [C0603L]
C257  22uF  [C0603L]
C258  22uF  [C0603L]
C259  33pF  [C0402L]
C260  100nF  [C0402L]
C261  100pF  [C0402L]
C262  33pF  [C0402L]
C263  10uF  [C0603L]
C264  1uF  [C0402L]
C265  6.8pF  [C0402L]
C266  22uF  [C0603L]
C267  22uF  [C0603L]
C271  33pF  [C0402L]
C272  33pF  [C0402L]
C273  33pF  [C0402L]
C274  22uF  [C0603L]
C275  22uF  [C0603L]
C276  22uF  [C0603L]
C277  22uF  [C0603L]
C278  100nF  [C0402L]
C482  10pF  [C0402L]
C483  33pF  [C0402L]
C484  100nF  [C0402L]
C485  10pF  [C0402L]
D94  ES0402V014CT  [V0402]
D95  ES0402V014CT  [V0402]
D96  ES0402V014CT  [V0402]
D97  ES0402V014CT  [V0402]
H5  HOLE  [mtg250_600]
J41  MINI-PCIE-S52-H80  [M_MINIPCIE_SOCKET_CK]
L48  UPZ1608E101-3R0TF  [L0603]
L49  1uH/3.5A  [L2520]
LED2  RED LED0603  [LED0603]
Q16  DTC143ZE  [SOT523]
R325  22R  [R0402L]
R326  22R  [R0402L]
R327  22R  [R0402L]
R328  0R  [R0402L]
R329  22R  [R0402L]
R330  10K  [R0402L]
R331  0R  [R0402L]
R332  0R  [R0402L]
R333  0R  [R0402L]
R334  1K  [R0402L]
R335  0R  [R0402L]
R336  0R  [R0402L]
R337  10K  [R0402L]
R338  100K  [R0402L]
R339  15K  [R0402L]
R340  200K  [R0402L]
R341  37.4K  [R0402L]
R342  10K  [R0402L]
R376  22R  [R0402L]
SIM1  SIM  [SIM-91288-021]
U36  NC/PCIE_M2_NGFF-B-KEY  [PCIE_M2_NGFF-B-KEY]
U37  TLV62569DBVR  [SOT23-5]
sheet P23. IO-PCA9593
C268  1uF  [C0402L]
C269  1uF  [C0402L]
R343  22R  [R0402L]
R344  22R  [R0402L]
R345  NC/22R  [R0402L]
R346  4.7K  [R0402L]
R347  4.7K  [R0402L]
R348  4.7K  [R0402L]
R349  4.7K  [R0402L]
R350  4.7K  [R0402L]
R351  4.7K  [R0402L]
R352  4.7K  [R0402L]
R353  4.7K  [R0402L]
R354  NC4.7K  [R0402L]
R355  NC/4.7K  [R0402L]
R356  4.7K  [R0402L]
R357  4.7K  [R0402L]
R358  4.7K  [R0402L]
R359  4.7K  [R0402L]
R360  4.7K  [R0402L]
R361  4.7K  [R0402L]
R362  4.7K  [R0402L]
R363  4.7K  [R0402L]
R364  NC/4.7K  [R0402L]
R365  NC/0R  [R0402L]
R366  0R  [R0402L]
U38  PCA9548PW  [PCA9539PW-TSSOP24]

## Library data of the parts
C36 C37 C40 C42 C200 C201 C203-C205 C207 C210 C213 C214 C216 C229 C231 C242 C245 C249 C251 C252 C254 C260 C278 C484 = C-0402: DSC1: ±10%; DSC2: 10V; DSC3: X7R; ID: 60; Manufacture: 三星|国巨|村田; Part Name: 贴片电容; Part Number: C020102120060; Price: 0.01
C38 C41 C43 C45 C263 = C-0603: DSC1: ±20%; DSC2: 10V; DSC3: X5R; ERP Number: 1010200076; ID: 71; Manufacture: 三星|国巨|村田; Part Name: 贴片电容; Part Number: C020102120071; Price: 0.05
C46 C47 C50 C51 C202 = C-0402: DSC1: ±10%; DSC2: 50V; DSC3: X7R; ERP Number: 1010200077; ID: 57; Manufacture: 三星|国巨|村田; Part Name: 贴片电容; Part Number: C020102120057; Price: 0.02
C48 = C-0805: DSC1: ±20%; DSC2: 10V; DSC3: X5R; ID: 75; Manufacture: 三星|国巨|村田; Part Name: 贴片电容; Part Number: C020102120075; Price: 0.11
D13 D14 D33-D37 D94-D102 = DI-ESD: DSC1: 双向; DSC2: Vdc=14V; DSC3: Vbr=300V; DSC4: Vc=30V; DSC5: Cj=0.25pF; ERP Number: 1010800023; ID: 2; Manufacture: AEM; Part Name: ESD; Part Number: C040502250002; Price: 0.06
D15-D17 = DI-ESD-MKT642U05: DSC2: Vdc=5V; DSC3: Vbr=6V; DSC4: Vc=16V; DSC5: Cj=0.35pF; ID: 8; Manufacture: 米客方德; Part Name: ESD; Part Number: C040502250008; Price: 0.15; Solder: 推荐
J5 = J-USB-4AFX2-DIP_1: DSC1: USB AF_18P 双层 DIP 90° 铁壳 弯脚  白色; DSC2: 17.6*14.5*15.7mm; DSC3: 通孔弯针; ID: 6; Part Name: USB连接器
J6 = SATA_DIP_0
J7 = J-H-2P: DSC1: 2p; DSC2: 2.5mm间距; DSC3: 通孔180度直针; DSC4: 米黄色胶壳 耐高温; DSC5: XH-2AK米(博穆精密); ID: 31; Part Name: XH; Part Number: J020602850001
L5 L6 L46 L47 = L-CMLS-ACM2012: DSC1: 90uH@100kHz; DSC2: 90Ω@100MHz; DSC3: 400mA; DSC4: DCR=300mΩ; DSC5: -40℃ ~ +125℃; DSC6: SMD_4P,2x1.2mm; ERP Number: 1010200196; ID: 1; Manufacture: 台庆; Part Name: 信号共模电感; Part Number: C060402360001; Price: 0.13
R28 R60 R61 R266 R287 R293 R294 R299 R301 R306 R307 R309 R323 R324 R330 R337 R342 = R-0402: DSC1: ±1%; DSC2: 1/16W; ERP Number: 1010200140; ID: 856; Part Name: 贴片电阻; Part Number: C011002080856; Price: 0.01
R29 R339 = R-0402: DSC1: ±1%; DSC2: 1/16W; ERP Number: 1010200458; ID: 875; Part Name: 贴片电阻; Part Number: C011002080875; Price: 0.01
R30-R33 R262 R267 R269 R270 R277 R300 R322 R328 R331-R333 R335 R336 R365-R367 R370-R373 = R-0402: DSC1: ±1%; DSC2: 1/16W; ID: 413; Part Name: 贴片电阻; Part Number: C011002080413; Price: 0.01
R34 R36 = R-0402: DSC1: ±1%; DSC2: 1/16W; ERP Number: 1010200459; ID: 1,059; Part Name: 贴片电阻; Part Number: C011002081059; Price: 0.01
R35 R37 R242 R243 R246 R247 R250 R251 R254-R258 R260 R261 R263 R264 R346-R364 = R-0402: DSC1: ±1%; DSC2: 1/16W; ERP Number: 1010200445; ID: 818; Part Name: 贴片电阻; Part Number: C011002080818; Price: 0.01
U4 U5 = U-SY6280AAC: DSC1: 低能耗电源开关; DSC2: 2.4-5.5V 2A; DSC3: 80m?; DSC4: -40~85℃; ERP Number: 1010100222; ID: 1; Manufacture: 矽力杰; Part Name: 功率开关; Part Number: C070402430001; Price: 0.42
J13 = J-H-6P: DSC1: 6p; DSC2: 2.0mm间距; DSC3: 通孔180度直针; DSC4: 米黄色胶壳 耐高温; DSC5: A2001WV-6P(CJT); ID: 15; Part Name: PH; Part Number: J020302820005
J14 = J-H-8P: DSC1: 8p; DSC2: 2.0mm间距; DSC3: 通孔180度直针; DSC4: 米黄色胶壳 耐高温; DSC5: A2001WV-8P(CJT); ID: 58; Part Name: PH
R62 R240 = R-0402: DSC1: ±1%; DSC2: 1/16W; ERP Number: 1010200450; ID: 630; Part Name: 贴片电阻; Part Number: C011002080630; Price: 0.01
SW1 = SW-K2-1109DE-C4SW-01: DSC1: 轻触开关 带支架侧键 插件 柄长4.8mm; DSC2: DIP,4.5*4.5mm*4.8mm; DSC3: K2-1109DE-C4SW-01(韩荣); ID: 9; Part Name: 轻触开关; Part Number: C180104013837
C192 C193 C239 C240 = C-0402: DSC1: ±5%; DSC2: 50V; DSC3: C0G; ERP Number: 1010200091; ID: 27; Manufacture: 三星|国巨|村田; Part Name: 贴片电容; Part Number: C020102120027; Price: 0.02
C194 C197 C211 C265 C494 C497 = C-0402: DSC1: ±0.25PF; DSC2: 50V; DSC3: C0G; ERP Number: 1010200056; ID: 18; Manufacture: 三星|国巨|村田; Part Name: 贴片电容; Part Number: C020102120018; Price: 0.01
C195 C196 C261 = C-0402: DSC1: ±5%; DSC2: 50V; DSC3: C0G; ERP Number: 1010200152; ID: 40; Manufacture: 三星|国巨|村田; Part Name: 贴片电容; Part Number: C020102120040; Price: 0.01
C199 C212 C215 = C-0402: DSC1: ±20%; DSC2: 10V; DSC3: X5R; ID: 67; Manufacture: 三星|国巨|村田; Part Name: 贴片电容; Part Number: C020102120067; Price: 0.04
C206 = C-1206: DSC1: ±10%; DSC2: 2KV; DSC3: X7R; ERP Number: 1010200094; ID: 77; Manufacture: 三星|国巨|村田; Part Name: 贴片电容; Part Number: C020102120077; Price: 0.17
C208 C209 C228 C232-C234 C236 C237 C241 C243 C244 C264 C268 C269 = C-0402: DSC1: ±10%; DSC2: 10V; DSC3: X5R; ERP Number: 1010200054; ID: 64; Manufacture: 三星|国巨|村田; Part Name: 贴片电容; Part Number: C020102120064; Price: 0.02
D73 D74 = DI-ESD-SRV05-4: DSC1: 单向; DSC2: Vrwm=5V; DSC3: VBR=6V; DSC4: Vc=13V; DSC5: Ipp=3.5A; DSC6: Ppp=45W; DSC7: Cj=0.36pF; ERP Number: 1010800050; ID: 15; Manufacture: 伯恩半导体; Part Name: TVS; Part Number: C040602260015; Price: 0.21; Solder: 量产
J31 = J-RJ45-HR911130C: DSC1: RJ45 内置千兆变压器带灯; DSC3: 90度插件; DSC4: HR911130C(汉仁); ID: 5; Part Name: RJ45; Part Number: J120103060005
L33 = L-IND: DSC1: ±20%; DSC2: Isat=2.3A; DSC3: Irms=2.1A; DSC4: 85mΩ; DSC5: 2.5*2.0*1.2mm; DSC6: WPN252012H2R2MTY01(顺络); ID: 14; Manufacture: 顺络; Part Name: 功率电感; Part Number: C060202340014; Price: 0.23
R230-R237 = R-0402: DSC1: ±1%; DSC2: 1/16W; ID: 453; Part Name: 贴片电阻; Part Number: C011002080453; Price: 0.01
R238 R239 = R-0402: DSC1: ±1%; DSC2: 1/16W; ID: 708; Part Name: 贴片电阻; Part Number: C011002080708; Price: 0.01
R241 = R-0402: DSC1: ±1%; DSC2: 1/16W; ID: 638; Part Name: 贴片电阻; Part Number: C011002080638; Price: 0.01
R244 R245 R248 R249 R252 R253 R271-R276 R278 R282 R284 R286 R291 R316 R317 R320 R321 R325-R327 R329 R343-R345 R376 R383-R385 = R-0402: DSC1: ±1%; DSC2: 1/16W; ID: 552; Part Name: 贴片电阻; Part Number: C011002080552; Price: 0.01
R259 = R-0402: DSC1: ±1%; DSC2: 1/16W; ERP Number: 1010200324; ID: 785; Part Name: 贴片电阻; Part Number: C011002080785; Price: 0.01
R265 = R-0805: DSC1: ±1%; DSC2: 1/8W; ERP Number: 1010200447; ID: 1,864; Part Name: 贴片电阻; Part Number: C011002081864; Price: 0.01
R268 = R-0402: DSC1: ±1%; DSC2: 1/16W; ID: 769; Part Name: 贴片电阻; Part Number: C011002080769; Price: 0.01
U25 = Ethernet_RTL8211F: Integrated 10/100/1000 Gigabit Ethernet Transceiver，Supports IEEE 802.3az-2010,; Created by: JJJ; Manufacturer: RealTek(瑞昱); Part Type: Ethernet; Priority: A
XT5 = XTAL-4P: DSC1: 40Ω; DSC2: ±10ppm; DSC3: 12pF; DSC4: -40℃~+85℃; DSC5: 3.2*2.5mm 4P; ID: 6; Manufacture: 泰晶; Part Name: 贴片无源晶振; Part Number: C050102290006; Price: 0.48
C217-C226 C235 C238 = C-0402: DSC1: ±10%; DSC2: 50V; DSC3: X7R; ERP Number: 1010200128; ID: 61; Manufacture: 三星|国巨|村田; Part Name: 贴片电容; Part Number: C020102120061; Price: 0.05
C227 C230 = C-0402: DSC1: ±10%; DSC2: 50V; DSC3: X7R; ERP Number: 1010200084; ID: 54; Manufacture: 三星|国巨|村田; Part Name: 贴片电容; Part Number: C020102120054; Price: 0.01
D75 D104-D106 = DI-TVS-D: DSC1: 双向; DSC2: Vrwm=12V; DSC3: VBR=13.3V; DSC4: Vc=19.9V; DSC5: Ipp=20.1A; DSC6: Ppp=400W; ERP Number: 1010800028; ID: 5; Manufacture: MDD|伯恩半导体; Part Name: TVS; Part Number: C040602260005
D78 D81 D85 D87 D89 D91 D103 = DI-TVS-BST23A122V: DSC1: 单向; DSC2: Vrwm=12V; DSC3: VBR=13.3V; DSC4: Vc=25V; DSC5: Ipp=12A; DSC6: Ppp=300W; DSC7: Cj=150pF; ID: 19; Manufacture: 伯恩半导体; Part Name: TVS; Part Number: C040602260019; Price: 0.19; Solder: 推荐
D82 D84 D86 D88 D90 D92 D93 D107 = DI-XI-S: DSC1: VR=30V; DSC2: IF=200mA; DSC3: VF=350mV/10mA; DSC4: IR=0.5uA; ID: 2; Manufacture: 乐山无线电; Part Name: 肖特基二级管; Part Number: C040202220002; Price: 0.05; Solder: 推荐
D83 = DI-XI-S: DSC1: VR=40V; DSC2: IF=1A; DSC3: VF=600mV/1A; DSC4: IR=1mA; ID: 5; Manufacture: 长电; Part Name: 肖特基二级管; Part Number: C040202220005; Price: 0.13
F2-F15 = FUSE-SMD1206: DSC1: 60V; DSC2: 0.1A; DSC3: SMD1206P010TF; DSC4: JK-NSMD010; ID: 5; Manufacture: BOURNS|金科; Part Name: 自恢复保险丝; Part Number: C160102670005; Price: 0.2
J32-J36 = J-A-4P: DSC1: 4p; DSC2: 2.0mm间距; DSC3: 卧贴; DSC4: 米黄色胶壳 耐高温; DSC5: A2001WR-S-4P(CJT); ID: 28; Part Name: PH; Part Number: J020302820060
J39 = J-A-5P: DSC1: 5p; DSC2: 2.0mm间距; DSC3: 卧贴; DSC4: 米黄色胶壳 耐高温; DSC5: A2001WR-S-5P(CJT); ID: 29; Part Name: PH; Part Number: J020302820061
L34-L45 = FB-0402: DSC1: 120Ω@100MHz; DSC2: 200mA; DSC3: DCR=400mΩ; DSC4: 低频信号; ERP Number: 1010200208; ID: 1; Manufacture: 顺络; Part Name: 贴片磁珠; Part Number: C060502370001; Price: 0.02
Q15 = N-MOS-Q: DSC1: Vds=30V; DSC2: Id=100mA; DSC3: Vgs(th)=1.5V; DSC4: Vgs=±20V; DSC5: pd=150mW; ERP Number: 1010800011; ID: 4; Manufacture: 先科; Part Name: N-MOS; Part Number: C030202190004; Price: 0.1
R288 R295 = R-0402: DSC1: ±1%; DSC2: 1/16W; ID: 893; Part Name: 贴片电阻; Part Number: C011002080893; Price: 0.01
R289 R292 R296 R298 = R-0603: DSC1: ±1%; DSC2: 1/10W; ID: 1,416; Part Name: 贴片电阻; Part Number: C011002081416; Price: 0.01
R290 R297 = R-1206: DSC1: ±1%; DSC2: 1/4W; ERP Number: 1010200271; ID: 1,999; Part Name: 贴片电阻; Part Number: C011002081999; Price: 0.01
R302 R305 R308 R312 R313 R318 R319 = R-0402: DSC1: ±1%; DSC2: 1/16W; ID: 778; Part Name: 贴片电阻; Part Number: C011002080778; Price: 0.01
R303 R304 R310 R311 = R-0603: DSC1: ±1%; DSC2: 1/10W; ID: 1,339; Part Name: 贴片电阻; Part Number: C011002081339; Price: 0.01
TP1-TP23 = TP-TEST: DSC1: 焊盘1mm; DSC2: 无孔; DSC3: 圆形; DSC4: 单面; ID: 3; Part Name: 测试点
U26 U27 = U-SP3232EEN-L-TR: DSC1: RS232 Transceiver up to 235kbps; DSC2: TSSOP-16，0.65mm Pitch; DSC3: -40℃~+85℃; ID: 49; Manufacture: EXAR(艾科嘉); Part Name: RS232/RS485芯片; Part Number: C100308133921; Price: 0.91
U28 U30 = U-MC74VHC1G04DFT2G: DSC1: 1位 反向 VCC=2V-5.5V; DSC2: SOT?353; DSC3: -55℃~+125℃; ERP Number: 1010100124; ID: 1; Manufacture: ON 安森美; Part Name: 逻辑芯片; Part Number: C080102450001; Price: 0.17
U29 U31 = U-SP485EEN-L-TR: DSC1: RS485 Transceiver ,up to 10Mbps; DSC2: SOIC-8_150mil，1.27mm Pitch; DSC3: -40℃~+85℃; ERP Number: 1010100125; ID: 24; Manufacture: EXAR(艾科嘉); Part Name: RS232/RS485芯片; Part Number: C100302510003; Price: 0.77
U32 U33 = U-TJA1057GT-3J: DSC1: CAN Transceiver, 5Mbps; DSC2: SOIC-8_150mil，1.27mm Pitch; DSC3: -40℃~+150℃; ERP Number: 1010100240; ID: 27; Manufacture: NXP; Part Name: CAN芯片; Part Number: C100402520002; Price: 4.6
J40 = J-A-2P: DSC1: 2p; DSC2: 1.25mm间距; DSC3: 立贴; DSC4: 米黄色胶壳 耐高温; DSC5: A1251WV-S-2P(CJT); ID: 6; Part Name: MX1.25T; Part Number: J020102800058
U34 = U-PCF85063ATT: DSC1: RTC,I2C, VCC=0.9-5.5V; DSC2: TSSOP8; DSC3: -40℃~+85℃; ID: 14; Manufacture: NXP; Part Name: RTC芯片
U35 = Sensor_MPU6500_1
XT6 = XTAL-2P: DSC1: 70kΩ; DSC2: ±20ppm; DSC3: 12.5pF; DSC4: -40℃~+85℃; DSC5: 3.2*1.5mm 2P; ID: 2; Manufacture: 泰晶; Part Name: 贴片无源晶振; Part Number: C050102290002; Price: 0.61
C246 C247 C253 C255-C258 C266 C267 C274-C277 = C-0603: DSC1: ±20%; DSC2: 6.3V; DSC3: X5R; ERP Number: 1010200133; ID: 72; Manufacture: 三星|国巨|村田; Part Name: 贴片电容; Part Number: C020102120072; Price: 0.06
C248 C259 C262 C271-C273 C483 = C-0402: DSC1: ±5%; DSC2: 50V; DSC3: C0G; ERP Number: 1010200087; ID: 33; Manufacture: 三星|国巨|村田; Part Name: 贴片电容; Part Number: C020102120033; Price: 0.01
C482 C485 = C-0402: DSC1: ±5%; DSC2: 50V; DSC3: C0G; ERP Number: 1010200151; ID: 21; Manufacture: 三星|国巨|村田; Part Name: 贴片电容; Part Number: C020102120021; Price: 0.01
H5 = HOLE
J41 = J-MINIPCIE-52P_0: DSC1: miniPCIE座子 H=8.0mm; DSC2: 52P; DSC3: 贴片; DSC4: 91304-80-052R2(UMaxconn); ID: 3; Part Name: 金手指连接器; Part Number: J050102900003
L48 = FB-0603: DSC1: 100Ω@100MHz; DSC2: 3A; DSC3: DCR=30mΩ; DSC4: 电源线; ERP Number: 1010200207; ID: 5; Manufacture: 顺络; Part Name: 贴片磁珠; Part Number: C060502370005; Price: 0.03
L49 = L-IND: DSC1: ±20%; DSC2: Isat=4.5A; DSC3: Irms=3.5A; DSC4: 37mΩ; DSC5: 2.5*2.0*1.2mm; DSC6: WPN252012E1R0MT(顺络); ID: 12; Manufacture: 顺络; Part Name: 功率电感; Part Number: C060202340012; Price: 0.22
LED2 = D-LED0603: DSC1: 红色LED，SMD,0603，VF=2V; DSC2: NCD0603R1(国星光电); DSC3: 19-217/R6C-AL1M2VY/3T(亿光); ERP Number: 1010800005; ID: 5; Part Name: LED; Part Number: C140202660001; Price: 0.08
Q16 = S-NPN: DSC1: NPN; DSC2: Ic=100mA; DSC3: Vce=50V; DSC4: 150mW; ERP Number: 1010800049; ID: 2; Manufacture: 长电; Part Name: 数字三极管; Part Number: C030302200002; Price: 0.08
R334 = R-0402: DSC1: ±1%; DSC2: 1/16W; ERP Number: 1010200113; ID: 742; Part Name: 贴片电阻; Part Number: C011002080742; Price: 0.01
R338 = R-0402: DSC1: ±1%; DSC2: 1/16W; ERP Number: 1010200137; ID: 976; Part Name: 贴片电阻; Part Number: C011002080976; Price: 0.01
R340 = R-0402: DSC1: ±1%; DSC2: 1/16W; ERP Number: 1010200139; ID: 1,009; Part Name: 贴片电阻; Part Number: C011002081009; Price: 0.01
R341 = R-0402: DSC1: ±1%; DSC2: 1/16W; ERP Number: 1010200444; ID: 922; Part Name: 贴片电阻; Part Number: C011002080922; Price: 0.01
SIM1 = J-SIM-021_0: DSC1: SIM卡座 91228 抽屉式 8P; DSC2: 31.0*25.1*26mm; DSC3: 贴片; DSC4: SIM-021(硕方); ERP Number: 1040100109; ID: 5; Part Name: SIM卡座; Part Number: J080202990002
U36 = PCIE_M2_NGFF-B-KEY_2
U37 = U-TLV62569DBVR: DSC1: Vi=2.5-5.5V; DSC2: Vo=0.6-5.5V; DSC3: Io=2A; DSC4: Vfb=0.6V; DSC5: 0.95; DSC6: 1.5MHz; DSC7: 同步降压 轻载效率 低Iq; ID: 3; Manufacture: TI; Part Name: DCDC; Part Number: C070202410003; Price: 0.3; Solder: 推荐
U38 = 5962-87786_1

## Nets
GND: C38.1 C41.1 C43.1 C45.1 C48.1 C192.1 C193.1 C194.1 C195.1 C196.1 C197.1 C199.1 C200.1 C201.1 C202.1 C203.1 C204.1 C205.1 C206.1 C207.1 C208.1 C209.1 C210.1 C211.1 C212.1 C213.1 C214.1 C215.1 C216.1 C217.1 C220.1 C221.1 C222.1 C225.1 C226.1 C227.1 C228.1 C229.1 C230.1 C231.1 C232.1 C233.1 C234.1 C235.1 C236.1 C237.1 C238.1 C239.2 C240.2 C241.1 C242.1 C243.1 C244.1 C245.1 C246.1 C247.1 C248.1 C252.1 C253.1 C254.1 C255.1 C256.1 C257.1 C258.1 C259.1 C260.1 C261.1 C262.1 C263.1 C264.1 C266.1 C267.1 C268.1 C269.1 C271.1 C272.1 C273.1 C274.1 C275.1 C276.1 C277.1 C278.1 C482.1 C483.1 C484.1 C485.1 C494.1 C497.1 D13.2(I/O1) D14.2(I/O1) D15.3 D15.8 D16.3 D16.8 D17.3 D17.8 D33.2(I/O1) D34.2(I/O1) D35.2(I/O1) D36.2(I/O1) D37.2(I/O1) D73.2 D74.2 D78.3 D81.3 D85.3 D87.3 D89.3 D91.3 D94.2(I/O1) D95.2(I/O1) D96.2(I/O1) D97.2(I/O1) D98.2(I/O1) D99.2(I/O1) D100.2(I/O1) D101.2(I/O1) D102.2(I/O1) D103.3 H5.1 J5.4(GND1) J5.7(GND2) J5.13(GND3) J5.16(GND4) J5.19(SHELL1) J5.20(SHELL2) J5.21(SHELL3) J5.22(SHELL4) J6.1(GND1) J6.4(GND2) J6.7(GND3) J6.8(GND4) J6.9(GND5) J7.2 J13.1 J13.6 J14.2 J14.8 J31.10(GND) J32.1 J32.5 J32.6 J33.1 J33.5 J33.6 J34.1 J34.5 J34.6 J35.1 J35.5 J35.6 J36.1 J36.5 J36.6 J39.3(6) J39.6(9) J39.7 J40.1 J40.3 J40.4 J41.4(GND) J41.9(GND) J41.15(GND) J41.18(GND) J41.21(GND) J41.26(GND) J41.27(GND) J41.29(GND) J41.34(GND) J41.35(GND) J41.37(GND) J41.40(GND) J41.43(GND) J41.50(GND) J41.55(MT3) J41.56(MT4) Q16.2 R29.2 R34.2 R35.2 R36.2 R37.2 R239.2 R241.2 R242.1 R246.1 R250.1 R254.1 R256.1 R257.1 R259.1 R260.1 R263.1 R265.1 R289.1 R293.2 R296.1 R299.2 R301.1 R307.1 R324.2 R338.2 R341.2 R365.2 R366.2 SIM1.C5(GND) SW1.2 SW1.3 TP16.1 TP17.1 TP18.1 TP19.1 TP20.1 TP21.1 TP22.1 TP23.1 U4.2(GND) U5.2(GND) U25.41(E_Pad) U26.15(GND) U27.15(GND) U28.3(G) U29.5(GND) U30.3(G) U31.5(GND) U32.2(GND) U33.2(GND) U34.4(VSS) U35.11(FSYNC) U35.18(GND) U35.20(RESV2) U35.25(E-PAD) U36.3(GND1) U36.5(GND2) U36.11(GND3) U36.27(GND4) U36.33(GND5) U36.39(GND6) U36.45(GND7) U36.51(GND8) U36.57(GND9) U36.71(GND10) U36.73(GND11/NC) U36.MH1 U36.MTG76(NC3) U36.MTG77(NC4) U37.2(GND) U38.12(GND) XT5.2 XT5.4 ; also on sheet 4 5 6 7 8 9 10 11 12 13 14 15 23
GND_EARTH: C206.2 J31.SH1 J31.SH2 R265.2 ; also on sheet 4 15
VBAT_RTC: D93.A J40.2
VCC3V3_PHY1: C212.2 C213.2 C214.2 C215.2 C216.2 R238.2 R243.2 R247.2 R266.1 R277.2 U25.11(AVDD33) U25.29(DVDD33) U25.40(AVDD33)
VCC5V0_SYS: C233.2 C236.2 C263.2 C264.2 D83.A J32.4 J33.4 J34.4 J35.4 J36.4 R306.1 R309.1 R367.1 U32.3(VCC) U33.3(VCC) U37.4(VIN) ; also on sheet 4 5 7 8 10 11 12 13
VCC5V0_USB_HOST1: C43.2 D14.1(I/O2) J5.10(VBUS2) U5.1(VOUT)
VCC5V0_USB_OTG0: C38.2 D13.1(I/O2) J5.1(VBUS1) R28.2 U4.1(VOUT)
VCC_1V8: R60.1 R61.1 R269.1 ; also on sheet 5 13 14 15 23
VCC_3V8: C246.2 C247.2 C248.2 C253.2 C254.2 C255.2 C256.2 C257.2 C258.2 C259.2 C265.2 C266.2 C267.2 C273.2 C274.2 C275.2 C276.2 C277.2 C278.2 C482.2 C483.2 C484.2 C485.2 J41.2(VCC3V3) J41.24(NC3) J41.39(VCC3V3) J41.41(VCC3V3) J41.52(VCC3V3) L49.2 R334.1 R337.1 R340.1 U36.2(VBAT1) U36.4(VBAT2) U36.70(VBAT3) U36.72(VBAT4) U36.74(VBAT5)
VCC_485: C228.2 C232.2 D83.C R292.2 R298.2 U29.8(VCC) U31.8(VCC)
VCC_SIM: C260.2 C261.2 D97.1(I/O2) L48.2 R330.2 R339.2 SIM1.C1(VDD) U36.36(UIM_PWR)
VCCIO_PHY1: C208.2 C209.2 C210.2 R251.2 R255.2 R258.2 R261.2 R264.2 R268.2 R269.2 R270.2 U25.28(DVDD_RG) ; also on sheet 15
VCCIO_WL: Q15.1(GATE) R305.1 R308.1 ; also on sheet 23
VDD10_PHY1: C199.2 C200.2 C201.2 C203.2 C204.2 C205.2 L33.2 U25.3(AVDD10) U25.8(AVDD10) U25.21(DVDD10) U25.38(AVDD10)
VDD_3V3: C217.2 C222.2 C229.2 C231.2 C242.2 C243.2 C244.2 C268.2 D92.A R270.1 R277.1 R287.1 R294.1 R300.1 R302.2 R312.2 R313.2 R318.2 R319.2 R322.2 R323.1 R346.2 R347.2 R348.2 R349.2 R350.2 R351.2 R352.2 R353.2 R354.2 R355.2 R356.2 R357.2 R358.2 R359.2 R360.2 R361.2 R362.1 R363.1 R364.1 U26.16(VCC) U27.16(VCC) U28.5(V) U30.5(V) U35.8(VDDIO) U35.13(VDD) U38.24(VDD) ; also on sheet 4 6 7 8 9 10 11 12 13 14 15 23
VDD_RTC: C241.2 D92.C D93.C U34.8(VDD)
VDD_USB_5V: C41.2 C45.2 C48.2 J7.1 J14.1 U4.5(IN) U5.5(IN) ; also on sheet 4 7 9
4G_5G_RESET_: Q16.3 R376.2 U36.67(RESET#_(1V8))
4G_5G_RESET_GPIO3_A4: Q16.1 ; also on sheet 5
4G_LED_WANN#: J41.42(LED_WWAN) LED2.C(CATHODE)
CAN1_H: L46.1 U32.7(CANH)
CAN1_L: L46.2 U32.6(CANL)
CAN1_RX_M0: D90.A R302.1 ; also on sheet 5
CAN1_RX_M0_: D90.C U32.4(RXD)
CAN1_STB_IO: R301.2 U32.8(S)
CAN1_TX_M0: U32.1(TXD) ; also on sheet 5
CAN1H: D89.1 D105.A(I/O2) F10.1 L46.4 R304.1
CAN1H_: F10.2 J39.5(2) TP12.1
CAN1L: D89.2 D105.C(I/O1) F11.1 L46.3 R303.1
CAN1L_: F11.2 J39.4 TP13.1
CAN2_H: L47.1 U33.7(CANH)
CAN2_L: L47.2 U33.6(CANL)
CAN2_RX_M0: D107.A R305.2 ; also on sheet 5
CAN2_RX_M0_: D107.C R306.2 U33.4(RXD)
CAN2_STB_IO: R307.2 U33.8(S)
CAN2_TX_M0: Q15.2(SOURCE) R308.2 ; also on sheet 5
CAN2_TX_M0_: Q15.3(DRAIN) R309.2 U33.1(TXD)
CAN2H: D91.1 D106.A(I/O2) F12.1 L47.4 R311.1
CAN2H_: F12.2 J39.2(8) TP14.1
CAN2L: D91.2 D106.C(I/O1) F13.1 L47.3 R310.1
CAN2L_: F13.2 J39.1(10) TP15.1
FE2.1_DM7: R335.2 ; also on sheet 7
FE2.1_DM7_: J41.36(USB_D-) R335.1
FE2.1_DP7: R336.2 ; also on sheet 7
FE2.1_DP7_: J41.38(USB_D+) R336.1
GMAC1_INT/PMEB_GPIO3_C1: R262.2 ; also on sheet 5
GMAC1_MCLKINOUT_M1: C194.2 R240.1 R241.1 ; also on sheet 5
GMAC1_MDC_M1: U25.13(MDC) ; also on sheet 5
GMAC1_MDIO_M1: R268.1 U25.14(MDIO) ; also on sheet 5
GMAC1_RSTn_GPIO3_A6: R267.1 ; also on sheet 5
GMAC1_RXCLK_M1: C211.2 R275.2 ; also on sheet 5
GMAC1_RXD0_M1: R271.2 ; also on sheet 5
GMAC1_RXD1_M1: R272.2 ; also on sheet 5
GMAC1_RXD2_M1: R273.2 ; also on sheet 5
GMAC1_RXD3_M1: R274.2 ; also on sheet 5
GMAC1_RXDV_CRS_M1: R276.2 ; also on sheet 5
GMAC1_TXCLK_M1: C494.2 R253.1 ; also on sheet 5
GMAC1_TXCLK_M1_: C197.2 R253.2 U25.20(TXC)
GMAC1_TXD0_M1: R244.1 ; also on sheet 5
GMAC1_TXD0_M1_: R244.2 U25.18(TXD0)
GMAC1_TXD1_M1: R245.1 ; also on sheet 5
GMAC1_TXD1_M1_: R245.2 U25.17(TXD1)
GMAC1_TXD2_M1: R248.1 ; also on sheet 5
GMAC1_TXD2_M1_: R248.2 U25.16(TXD2)
GMAC1_TXD3_M1: R249.1 ; also on sheet 5
GMAC1_TXD3_M1_: R249.2 U25.15(TXD3)
GMAC1_TXEN_M1: R252.1 ; also on sheet 5
GMAC1_TXEN_M1_: R252.2 U25.19(TXCTL)
I2C1_SCL: R313.1 R316.2 R344.1 ; also on sheet 5
I2C1_SCL_RTC: R316.1 U34.6(SCL)
I2C1_SDA: R312.1 R317.2 R343.1 ; also on sheet 5
I2C1_SDA_RTC: R317.1 U34.5(SDA)
I2C2_SCL_M0: R318.1 R320.1 ; also on sheet 5
I2C2_SDA_M0: R319.1 R321.1 ; also on sheet 5
LAN1_A+: D74.6 J31.2(MDI_0+) R237.2
LAN1_A-: D74.1 J31.3(MDI_0-) R236.2
LAN1_B+: D74.3 J31.4(MDI_1+) R235.2
LAN1_B-: D74.4 J31.7(MDI_1-) R234.2
LAN1_C+: D73.6 J31.5(MDI_2+) R233.2
LAN1_C-: D73.1 J31.6(MDI_2-) R232.2
LAN1_D+: D73.3 J31.8(MDI_3+) R231.2
LAN1_D-: D73.4 J31.9(MDI_3-) R230.2
LCM_VIO_EN: R359.1 U38.15(IO1_2) ; also on sheet 10 13
MPU6500_AD0: R323.2 R324.1 U35.9(SDO/AD0)
PCA9539_A0: R364.2 R366.1 U38.21(A0)
PCA9539_A1: R363.2 R365.1 U38.2(A1)
PCA9539_I2C_SCL: R344.2 U38.22(SCL)
PCA9539_I2C_SDA: R343.2 U38.23(SDA)
PCA9539_INT: R345.2 U38.1(INT#)
PCA9539_INT_GPIO4_C4: R345.1 ; also on sheet 5
PCA9539_IO0_0: R36.1 R353.1 U5.4(EN) U38.4(IO0_0)
PCA9539_IO0_1: R352.1 U38.5(IO0_1) ; also on sheet 7
PCA9539_IO0_2: R351.1 U38.6(IO0_2) ; also on sheet 7
PCA9539_IO0_3: R350.1 U38.7(IO0_3) ; also on sheet 7
PCA9539_IO0_4: R349.1 U38.8(IO0_4) ; also on sheet 7
PCA9539_IO0_5: R348.1 U38.9(IO0_5) ; also on sheet 7
PCA9539_IO0_6: R347.1 U38.10(IO0_6) ; also on sheet 7
PCA9539_IO0_7: R346.1 U38.11(IO0_7) ; also on sheet 23
PCA9539_IO1_0: R361.1 U38.13(IO1_0) ; also on sheet 8
PCA9539_IO1_1: R360.1 U38.14(IO1_1) ; also on sheet 8
PCA9539_IO1_3: R358.1 U38.16(IO1_3) ; also on sheet 13
PCA9539_IO1_4: R357.1 U38.17(IO1_4) ; also on sheet 7
PCA9539_IO1_5: R342.1 R356.1 U38.18(IO1_5)
PCA9539_IO1_6: R355.1 U38.19(IO1_6) ; also on sheet 10
PCA9539_IO1_7: R354.1 U38.20(IO1_7)
PCA9539_RST: C269.2 R362.2 U38.3(RST#)
PCIE20_REFCLKN: R331.2 ; also on sheet 5
PCIE20_REFCLKP: R328.2 ; also on sheet 5
PCIE20_RXN: R333.2 ; also on sheet 5
PCIE20_RXN_: R333.1 U36.41(PETN0)
PCIE20_RXP: R332.2 ; also on sheet 5
PCIE20_RXP_: R332.1 U36.43(PETP0)
PCIE20_TXN: C251.2 ; also on sheet 5
PCIE20_TXN_: C251.1 U36.47(PERN0)
PCIE20_TXP: C249.2 ; also on sheet 5
PCIE20_TXP_: C249.1 U36.49(PERP0)
PHY1_CLKOUT125: R240.2 U25.35(CLKOUT)
PHY1_G_LED-: J31.12(G_LED-) R239.1
PHY1_LED0/CFG_EXT: R242.2 R243.1 U25.32(LED0/CFG_EXT)
PHY1_LED1/CFG_LDO0: C196.2 J31.11(G_LED+) R250.2 U25.33(LED1/CFG_LDO0)
PHY1_LED2/CFG_LDO1: C195.2 J31.13(Y_LED-) R246.2 R247.1 U25.34(LED2/CFG_LDO1)
PHY1_MDI0+: R237.1 U25.1(MDI[0]+)
PHY1_MDI0-: R236.1 U25.2(MDI[0]-)
PHY1_MDI1+: R235.1 U25.4(MDI[1]+)
PHY1_MDI1-: R234.1 U25.5(MDI[1]-)
PHY1_MDI2+: R233.1 U25.6(MDI[2]+)
PHY1_MDI2-: R232.1 U25.7(MDI[2]-)
PHY1_MDI3+: R231.1 U25.9(MDI[3]+)
PHY1_MDI3-: R230.1 U25.10(MDI[3]-)
PHY1_REG_OUT: L33.1 U25.30(REG_OUT)
PHY1_RSTn: C207.2 R266.2 R267.2 U25.12(PHYRSTB)
PHY1_RXCLK/PHYAD1: C497.2 R254.2 R255.1 R275.1 U25.27(RXC/PHYAD1)
PHY1_RXD0/RXDLY: R257.2 R258.1 R271.1 U25.25(RXD0/RXDLY)
PHY1_RXD1/TXDLY: R260.2 R261.1 R272.1 U25.24(RXD1/TXDLY)
PHY1_RXD2/PLLOFF: R263.2 R264.1 R273.1 U25.23(RXD2/PLLOFF)
PHY1_RXD3/PHYAD0: R251.1 R274.1 U25.22(RXD3/PHYAD0)
PHY1_RXDV/PHYAD2: R256.2 R276.1 U25.26(RXCTL/PHYAD2)
PHY1_XTALIN: C192.2 U25.36(XTAL_IN) XT5.3
PHY1_XTALOUT: C193.2 U25.37(XTAL_OUT/EXT_CLK) XT5.1
PHY1_Y_LED+: J31.14(Y_LED+) R238.1
PWM7_IR: D102.1(I/O2) J14.7 ; also on sheet 5
REFCLKN_: R331.1 U36.53(PEFCLKN)
REFCLKP_: R328.1 U36.55(PEFCLKP)
RK809_PWRON: D34.1(I/O2) J13.2 ; also on sheet 5
RS485_5_DM: L42.1 R289.2 U29.7(B)
RS485_5_DP: L43.1 R292.1 U29.6(A)
RS485_5_RW_EN: R293.1 U28.4 U29.2(\\~{R}E) U29.3(DE)
RS485_7_DM: L44.1 R296.2 U31.7(B)
RS485_7_DP: L45.1 R298.1 U31.6(A)
RS485_7_RW_EN: R299.1 U30.4 U31.2(\\~{R}E) U31.3(DE)
RSET1: R259.2 U25.39(RSET)
RTCIC_32KOUT: U34.7(CLKOUT) ; also on sheet 23
S0RX: D103.2 F14.1 L41.2 R383.2
S0RX_: F14.2 J32.3 TP3.1
S0TX: D103.1 F15.1 L40.2 R278.2
S0TX_: F15.2 J32.2 TP2.1
S3RX_M1: D78.2 F2.1 L35.2 R384.2
S3RX_M1_: F2.2 J33.3 TP4.1
S3TX_M1: D78.1 F3.1 L34.2 R282.2
S3TX_M1_: F3.2 J33.2 TP5.1
S4RX_M1: D81.2 F4.1 L37.2 R385.2
S4RX_M1_: F4.2 J34.3 TP6.1
S4TX_M1: D81.1 F5.1 L36.2 R284.2
S4TX_M1_: F5.2 J34.2 TP7.1
S5RX_M1: D82.C U29.1(RO)
S5RX_M1/RS485-A5: D75.C(I/O1) D85.2 F6.1 L39.2 L43.2 R290.2
S5RX_M1_: F6.2 J35.3 TP8.1
S5TX_M1: R286.2 U29.4(DI)
S5TX_M1/RS485-B5: D75.A(I/O2) D85.1 F7.1 L38.2 L42.2 R290.1
S5TX_M1_: F7.2 J35.2 TP9.1
S7RX_M1: D86.C U31.1(RO)
S7RX_M1/RS485-A7: D87.2 D104.C(I/O1) F8.1 L45.2 R297.2
S7RX_M1_: F8.2 J36.3 TP10.1
S7TX_M1: R291.2 U31.4(DI)
S7TX_M1/RS485-B7: D87.1 D104.A(I/O2) F9.1 L44.2 R297.1
S7TX_M1_: F9.2 J36.2 TP11.1
SARADC_VIN0_KEY/RECOVERY: D33.1(I/O2) R62.1 ; also on sheet 5
SARADC_VIN2_HP_HOOK: D35.1(I/O2) J13.3 ; also on sheet 5 8
SARADC_VIN4: D36.1(I/O2) J13.4 R60.2 ; also on sheet 5
SARADC_VIN5: D37.1(I/O2) J13.5 R61.2 ; also on sheet 5
SATA1_RXN: C50.1 J6.5(RXN)
SATA1_RXP: C51.1 J6.6(RXP)
SATA1_TXN: C47.1 J6.3(TXN)
SATA1_TXP: C46.1 J6.2(TXP)
SIM_CLK: C271.2 D95.1(I/O2) R327.2 SIM1.C3(CLK) U36.32(UIM_CLK)
SIM_DATA: C262.2 D96.1(I/O2) R326.2 R339.1 SIM1.C7(DATA) U36.34(UIM_DATA)
SIM_DET: R325.1
SIM_RST: C272.2 D94.1(I/O2) R329.2 R330.1 SIM1.C2(RESET) U36.30(UIM_RESET)
SPI3_CLK_M1: D98.1(I/O2) J14.3 ; also on sheet 5
SPI3_CS0_M1: D101.1(I/O2) J14.6 ; also on sheet 5
SPI3_MISO_M1: D100.1(I/O2) J14.5 ; also on sheet 5
SPI3_MOSI_M1: D99.1(I/O2) J14.4 ; also on sheet 5
UART0_RX: R372.1 R383.1 ; also on sheet 5
UART0_RX_: R372.2 U27.9(R2OUT)
UART0_TX: R278.1 U27.10(T2IN) ; also on sheet 5
UART3_RX_M1: R370.1 R384.1 ; also on sheet 5
UART3_RX_M1_: R370.2 U26.12(R1OUT)
UART3_TX_M1: R282.1 U26.11(T1IN) ; also on sheet 5
UART4_RX_M1: R371.1 R385.1 ; also on sheet 5
UART4_RX_M1_: R371.2 U26.9(R2OUT)
UART4_TX_M1: R284.1 U26.10(T2IN) ; also on sheet 5
UART5_RX_M1: D82.A R287.2 R373.1 ; also on sheet 5
UART5_RX_M1_: R373.2 U27.12(R1OUT)
UART5_TX_M1: D84.C R286.1 R288.1 U27.11(T1IN) ; also on sheet 5
UART7_RX_M1: D86.A R294.2 ; also on sheet 5
UART7_TX_M1: D88.C R291.1 R295.1 ; also on sheet 5
USB3_HOST1_DM: L6.1 ; also on sheet 5
USB3_HOST1_DM_: D15.5 D15.6 J5.11(2D-) L6.4
USB3_HOST1_DP: L6.2 ; also on sheet 5
USB3_HOST1_DP_: D15.4 D15.7 J5.12(2D+) L6.3
USB3_HOST1_SSRXN: C50.2 R32.1 ; also on sheet 5
USB3_HOST1_SSRXN_: D17.4 D17.7 J5.14(RX2-) R32.2
USB3_HOST1_SSRXP: C51.2 R33.1 ; also on sheet 5
USB3_HOST1_SSRXP_: D17.5 D17.6 J5.15(RX+) R33.2
USB3_HOST1_SSTXN: C40.1 C47.2 ; also on sheet 5
USB3_HOST1_SSTXN_: C40.2 D16.4 D16.7 J5.17(TX2-)
USB3_HOST1_SSTXP: C42.1 C46.2 ; also on sheet 5
USB3_HOST1_SSTXP_: C42.2 D16.5 D16.6 J5.18(TX2+)
USB3_OTG0_DM: L5.1 ; also on sheet 5
USB3_OTG0_DM_: D15.2 D15.9 J5.2(1D-) L5.4
USB3_OTG0_DP: L5.2 ; also on sheet 5
USB3_OTG0_DP_: D15.1 D15.10 J5.3(1D+) L5.3
USB3_OTG0_SSRXN: R30.1 ; also on sheet 5
USB3_OTG0_SSRXN_: D17.1 D17.10 J5.5(RX1-) R30.2
USB3_OTG0_SSRXP: R31.1 ; also on sheet 5
USB3_OTG0_SSRXP_: D17.2 D17.9 J5.6(RX1+) R31.2
USB3_OTG0_SSTXN: C36.1 ; also on sheet 5
USB3_OTG0_SSTXN_: C36.2 D16.1 D16.10 J5.8(TX1-)
USB3_OTG0_SSTXP: C37.1 ; also on sheet 5
USB3_OTG0_SSTXP_: C37.2 D16.2 D16.9 J5.9(TX1+)
USB3_OTG0_VBUSDET: R28.1 R29.1 ; also on sheet 5
USB_OTG_PWREN_H: R34.1 U4.4(EN) ; also on sheet 5
N67123537: R35.1 U4.3(OCB)
N67928236: C218.2 U26.1(C1+)
N67928238: C218.1 U26.3(C1-)
N67928242: C219.2 U26.4(C2+)
N67928244: C219.1 U26.5(C2-)
N67928270: C220.2 U26.2(V+)
N67928274: C221.2 U26.6(V-)
N68112138: R37.1 U5.3(OCB)
N68149060: R62.2 SW1.1
N68226715: L34.1 U26.14(T1OUT)
N68226717: L35.1 U26.13(R1IN)
N68226719: L36.1 U26.7(T2OUT)
N68226721: L37.1 U26.8(R2IN)
N68540703: R262.1 U25.31(INTB/PMEB)
N68563618: C239.1 U34.1(OSCI) XT6.1
N68563661: C240.1 U34.2(OSCO) XT6.2
N68600227: J41.10(USIM_IO) R326.1
N68600229: J41.12(USIM_CLK) R327.1
N68600231: J41.14(USIM_RESET) R329.1
N68600309: J41.8(VREG_USIM) L48.1
N68721096: R325.2 U36.66(SIM1_DETECT_(1V8))
N68721887: R342.2 U37.1(EN)
N68721931: L49.1 U37.3(SW)
N68721933: C265.1 R340.2 R341.1 U37.5(FB)
N68723170: C252.2 R337.2 R338.1 U36.6(FUL_CARD_P/OWER_OFF#_(3V3/1V8))
N68753609: R321.2 U35.24(SDA/SDI)
N68753612: R322.1 U35.22(nCS)
N68753720: R320.2 U35.23(SCL/SCLK)
N68753740: TP1.1 U35.12(INT)
N68754791: C245.2 U35.10(REGOUT)
N68825811: LED2.A(ANODE) R334.2
N68865571: C227.2 D84.A R288.2 U28.2
N68866830: C230.2 D88.A R295.2 U30.2
N68869057: C223.2 U27.1(C1+)
N68869059: C223.1 U27.3(C1-)
N68869063: C224.2 U27.4(C2+)
N68869065: C224.1 U27.5(C2-)
N68869069: C225.2 U27.2(V+)
N68869073: C226.2 U27.6(V-)
N68869089: L38.1 U27.14(T1OUT)
N68869091: L39.1 U27.13(R1IN)
N68869093: L40.1 U27.7(T2OUT)
N68869095: L41.1 U27.8(R2IN)
N68871128: C235.2 R303.2 R304.2
N68871171: C234.2 R300.2 U32.5(VIO/NC)
N68877118: C238.2 R310.2 R311.2
N68877190: C237.2 R367.2 U33.5(VIO/NC)
N68886075: C202.2 J31.1(CT1/2/3/4)
N69126369: J41.22(PERST_N) R376.1

Not connected (* = marked no-connect by the designer): D73 5*; D74 5*; J41 1(MICP)* 3(MICN)* 5(EARP)* 6(NC1)* 7(EARN)* 11(UART1_RX)* 13(UART1_TX)* 16(NC2)* 17(UART1_R1)* 19(WAKEUP_N)* 20(W_DISABLE_N)* 23(UART1_CTS)* 25(UART1_RFR)* 28(NC4)* 30(UART2_RFR)* 31(UART1_DTR)* 32(UART2_CTS)* 33(UART1_DCD)* 44(UART2_RX)* 45(AUX_PCM_CLK)* 46(UART2_TX)* 47(AUX_PCM_DOUT)* 48(NC5)* 49(AUX_PCM_DIN)* 51(AUX_PCM_SYNC)* 53(MT1) 54(MT2); SIM1 C6(VPP)* CD1 CD2; U28 1(NC); U30 1(NC); U34 3(\~{IN}T); U35 1(NC#1)* 2(NC#2)* 3(NC#3)* 4(NC#4)* 5(NC#5)* 6(NC#6)* 7(AUX_CL)* 14(NC#7)* 15(NC#8)* 16(NC#9)* 17(NC#10)* 19(RESV1)* 21(AUX_DA)*; U36 1(CONFIG_3) 7(USB_D+) 8(W_DISABLE1#_(3V3/1V8)) 9(USB_D-) 10(LED#1_(3V3/1V8)) 20(AUDIO_0/PCM_SYNC/I2S_WA_(1V8)) 21(CONFIG0) 22(AUDIO_1/PCM_IN/I2S_DIN_(1V8)) 23(WAKE_ON_W/WAN_(3V3/1V8)) 24(AUDIO_2/PCM_OUT/I2S_DOUT_(1V8)) 25(DPR) 26(W_DISABLE2#_(3V3/1V8)) 28(AUDIO_3/PCM_CLK/I2S_CLK_(1V8)) 29(USB_SS_TX-) 31(USB_SS_TX+) 35(USB_SS_RX-) 37(USB_SS_RX+) 38(BT_EN_(1V8)) 40(I2C_SCL/SPI_CLK/UART_RTS_(1V8)) 42(I2C_SDA/SPI_CS/UART_CTS_(1V8)) 44(WLAN_EN_(1V8)) 46(GP_CLK/SI_INT_N_(1V8)) 48(WL_SLP_CLK_(1V8)) 50(PERST#_(1V8)) 52(CLKREQ#_(1V8)) 54(PEWAKE#_(1V8)) 56(I2S_MCLK/SI_RST_N_(1V8)) 58(UART_RX/SPI_MISO_(1V8)) 59(ANTCTL0_(1V8)) 60(UART_TX/SPI_MOSI_(1V8)) 61(ANTCTL1_(1V8)) 62(COEX_TX_(1V8)) 63(ANTCTL2_(1V8)) 64(COEX_RX_(1V8)) 65(ANTCTL3_(1V8)) 68(WL_PWR_EN_(1V8)) 69(CONFIG_1) 75(CONFIG_2) NC1 NC2

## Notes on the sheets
sheet 16
- Giga PHY1
- RGMII Power Source
- CFG_EXT
- CFG_LDO[1:0]
- External 3.3V
- 1'b1
- 2'b00
- External 1.8V
- 1'b1
- 2'b10
- Internal 1.8V(default)
- 1'b0
- 2'b10
- 3.3Vpp
- MAC <----- PHY
- Reserve for EMI.
- Reserve for EMI.
- VCC_PHY0_IO Voltage Config
- Close to SOC
- PHY Address Config
- PHY Address
- PHYAD[2:0]
- 1 (default)
- 3'b001
- Pull-up for additional 2ns delay to RXC for data latching
- Pull-up for additional 2ns delay to TXC for data latching
- Pull-up to disable PLL @ ALDPS mode(Low power mode)
- Close to PIN21
- Close to PIN30
- RTL8211F-CG(SW Mode)
- RTL8211FI-CG(SW Mode)Industrial
- Close to PIN3,8,38
- RTL8211F-CG(SW Mode)
- RTL8211FI-CG(SW Mode)Industrial
- Note:
- According to the actual
  choice of mounted
  Cannot be mounted
  at the same time
- PHYRSTB is 3.3V IO
- Close to PIN28
- Close to PIN11,40
- Close to PHY
- Close to PIN29
sheet 18
- RTC IC
- Gyroscope+G-sensor
sheet 19
- USB3.0
- SATA3.0 Port1
- SATA3.0 Power
- And USB3 HOST1 option, Can support SATA1+USB2 HOST1
- Diff 100 Ohm ±10%
- Diff 100 Ohm ±10%
- Diff 100 Ohm ±10%
- Diff 100 Ohm ±10%
- NOTES:
  1:The SATA differential trace impedance is 100 OHM.
  The SATA trace length is less than 5 inch.
  2:10nF close to connector
sheet 20
- 5G module PCIe
- 4G module PCIe
- 4G/5G_POWER
- SIM_CARD
sheet 21
- Key Array
- ADC=9
- IR_IN
sheet 22
- UART
- RS232-3
- 3.3V
- 3.3V
- 3.3V
- 3.3V
- 3.3V
- 3.3V
- 1.8V
- RS232-4
- RS485-5
- RS485-7
- CAN1_M0
- CAN2_M0
